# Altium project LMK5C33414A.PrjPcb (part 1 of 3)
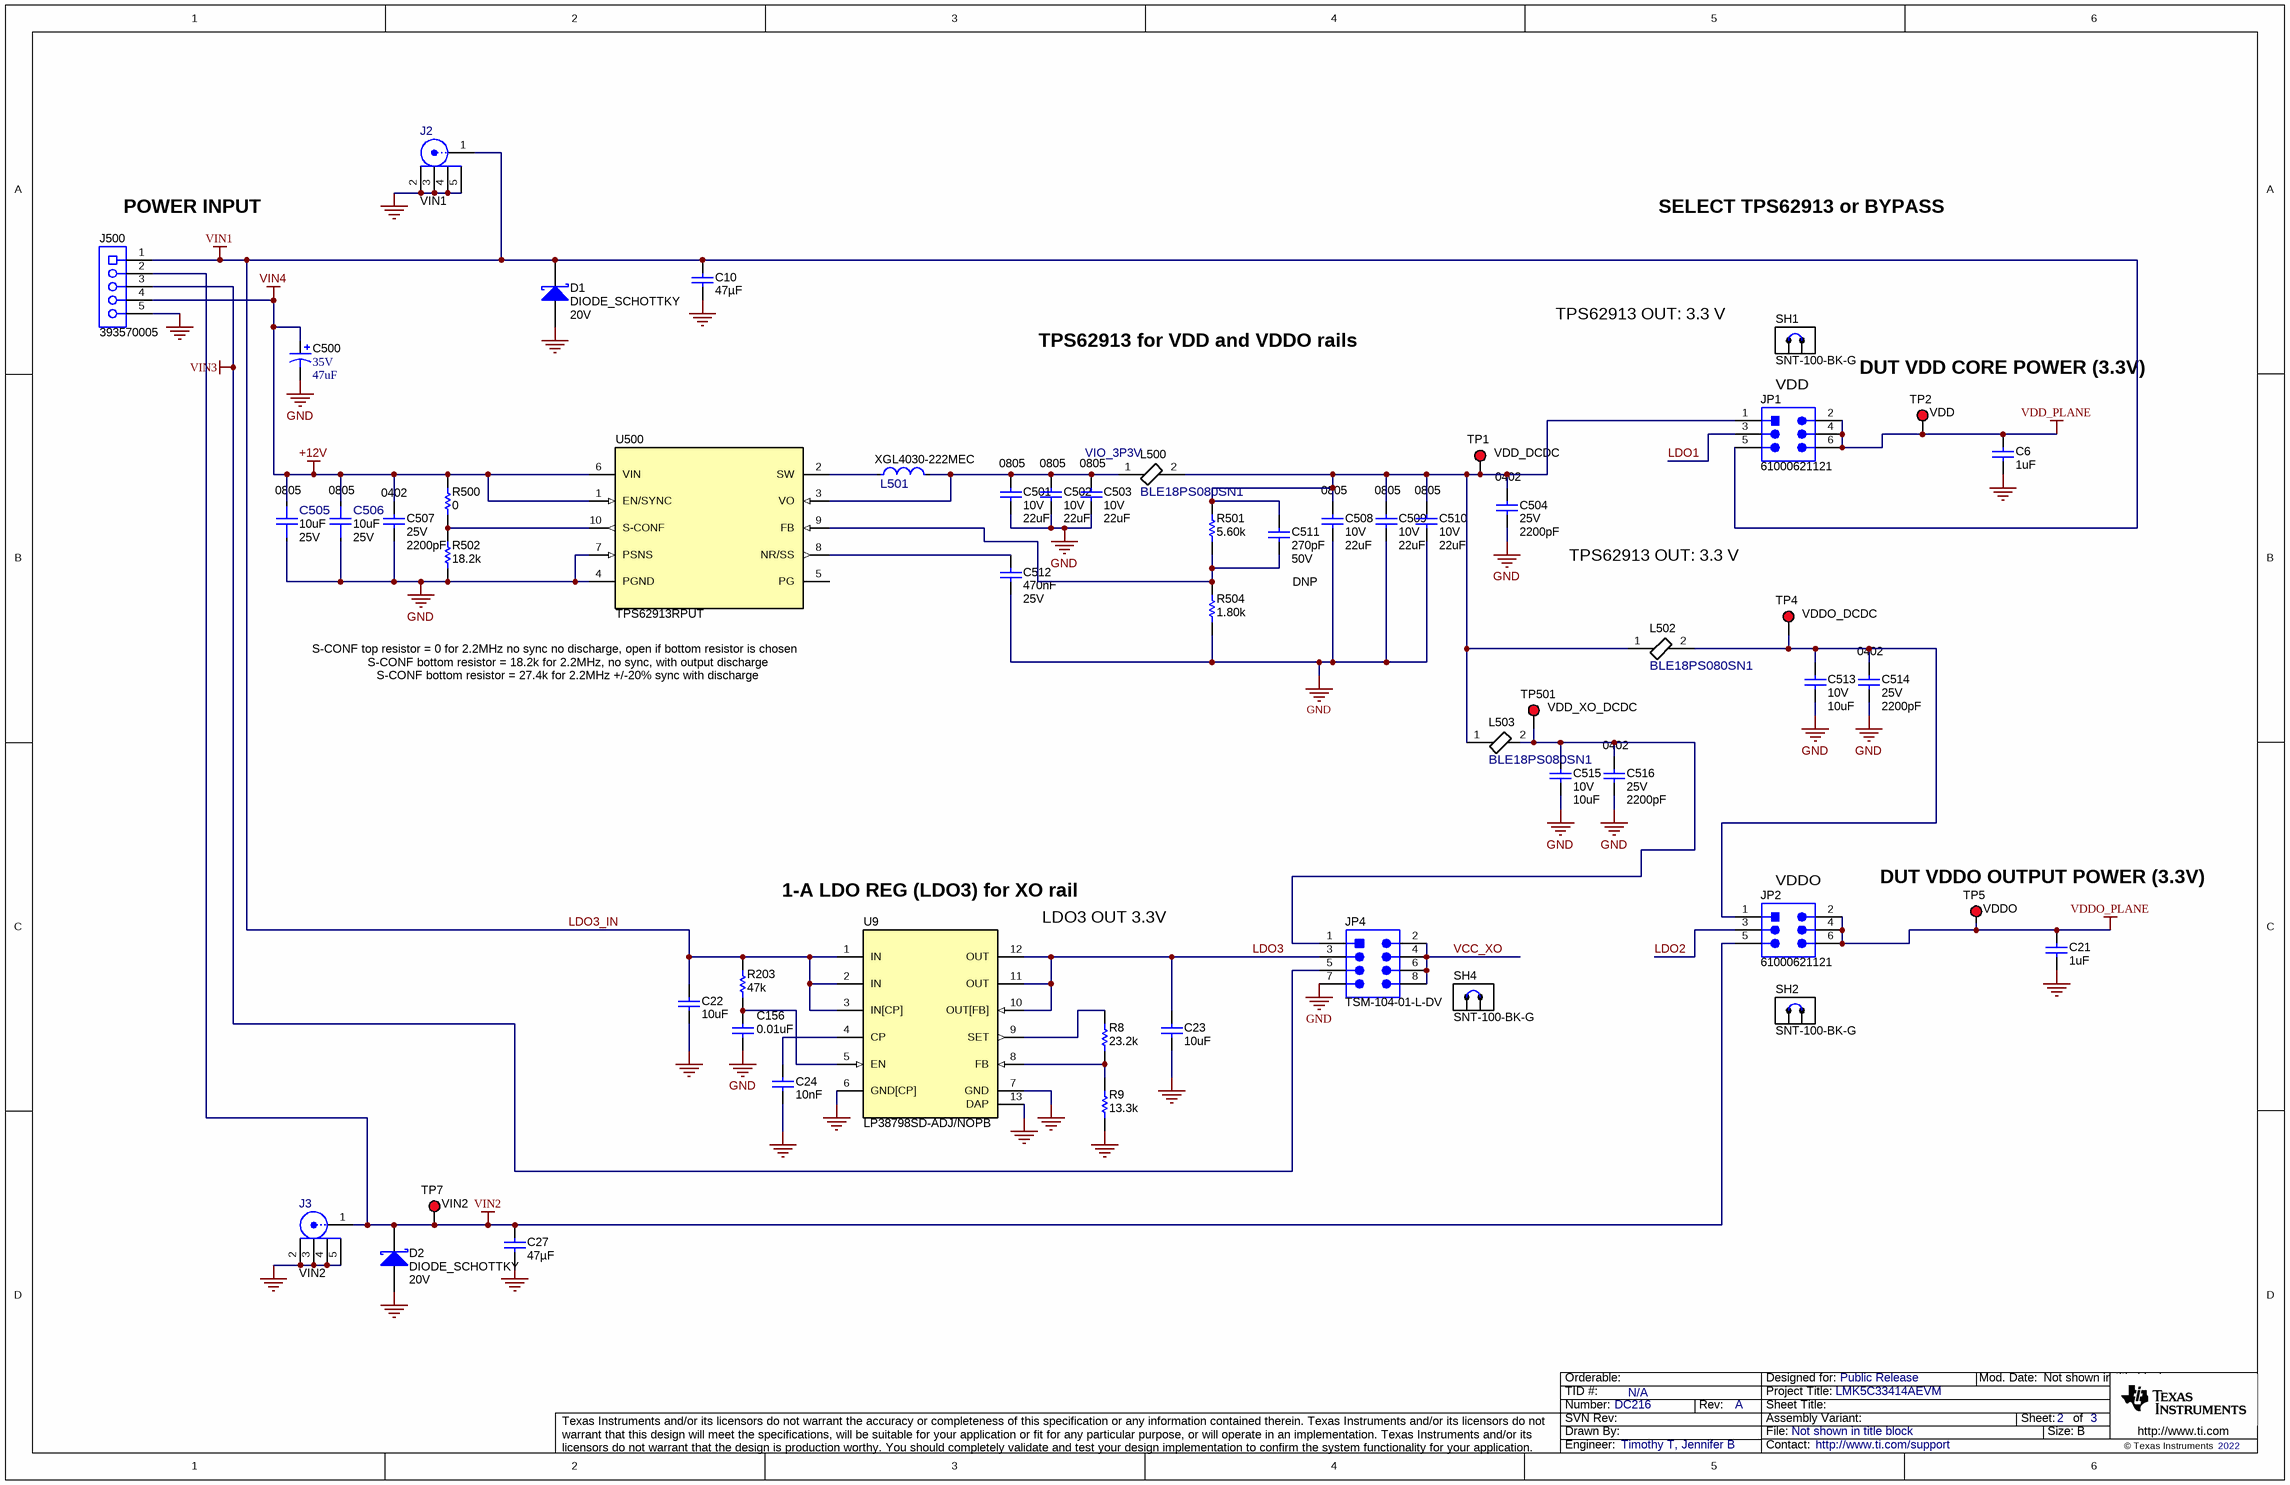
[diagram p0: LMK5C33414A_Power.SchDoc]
CopyrightYear: 2022; PCB_Layout: Timothy T, Jennifer B; PCB_Rev: A; PRJ_Customer: Public Release; PRJ_Engineer: Timothy T, Jennifer B; PRJ_Number: DC216; PRJ_Title: LMK5C33414AEVM; SCH_Rev: A; TechSupport: http://www.ti.com/support; TID: N/A
12 sheets, 526 parts. Net scope: global (net labels, ports and power ports of the same name join across sheets).
Board file: LMK5C33414A_PCB.PcbDoc
Sheets:
  LMK5C33414A_Power.SchDoc
  LMK5C33414A_Power_Alternate.SchDoc
  LMK5C33414A_PowerDist.SchDoc
  LMK5C33414A_XO.SchDoc
  LMK5C33414A_Inputs.SchDoc
  LMK5C33414A_DUT.SchDoc
  LMK5C33414A_Logic.SchDoc
  LMK5C33414A_Outputs_A.SchDoc
  LMK5C33414A_Outputs_B.SchDoc
  LMK5C33414A_Outputs_C.SchDoc
  LMK5C33414A_USB2ANY.SchDoc
  LMK5C33414A_Hardware.SchDoc

## Sheet LMK5C33414A_Power.SchDoc
size 431 x 279 mm; Date: Not shown in title block; ApprovedBy: Not shown in title block; CheckedBy: Not shown in title block; Author: Not shown in title block; CompanyName: Not shown in title block; Engineer: Not shown in title block; Organization: Not shown in title block; Address1: Not shown in title block; Address2: Not shown in title block; Address3: Not shown in title block; Address4: Not shown in title block; DocumentNumber: 2; Revision: Use project parameter SCH_Rev; SheetNumber: 2; SheetTotal: 3; PageSetup: Record=PageOptions¦CenterHorizontal=True¦CenterVertical=True¦PrintScale=1.00¦XCorrection=1.00¦YCorrection=1.00¦PrintKind=0¦BorderSize=5000000¦LeftOffset=0¦BottomOffset=0¦Orientation=2¦PaperLength=1000¦PaperWidth=1000¦Scale=100¦PaperSource=15¦PrintQuality=600¦MediaType=1¦DitherType=10¦PaperKind=Letter¦PrintScaleMode=1

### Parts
C6  ValueDisplayed: 1uF  [0603]  (hidden comment: Capacitor)
C10  ValueDisplayed: 47µF  [0805_HV]  (hidden comment: GRM21BR61A476ME15L)
C21  ValueDisplayed: 1uF  [0603]  (hidden comment: Capacitor)
C22  ValueDisplayed: 10uF  [0603]  (hidden comment: Capacitor)
C23  ValueDisplayed: 10uF  [0603]  (hidden comment: Capacitor)
C24  ValueDisplayed: 10nF  [0603]  (hidden comment: Capacitor)
C27  ValueDisplayed: 47µF  [0805_HV]  (hidden comment: GRM21BR61A476ME15L)
C156  ValueDisplayed: 0.01uF  [0603]  (hidden comment: Capacitor)
C500  VDC_V: 35V  ValueDisplayed: 47uF  [7343-43]  (hidden comment: T495X476K035ATE300)
C501  Cap_Case: 0805  VDC_V: 10V  ValueDisplayed: 22uF  [0805L]  (hidden comment: C2012X7S1A226M125AC)
C502  Cap_Case: 0805  VDC_V: 10V  ValueDisplayed: 22uF  [0805L]  (hidden comment: C2012X7S1A226M125AC)
C503  Cap_Case: 0805  VDC_V: 10V  ValueDisplayed: 22uF  [0805L]  (hidden comment: C2012X7S1A226M125AC)
C504  VDC_V: 25V  ValueDisplayed: 2200pF  [0402]  (hidden comment: GRM155R71E222KA01D)
C505  PackageReference: 0805  ValueDisplayed: 10uF  VDC_V: 25V  [FP-C2012X7S1E106K125AC_0805-MFG]  (hidden comment: C2012X7S1E106K125AC)
C506  PackageReference: 0805  ValueDisplayed: 10uF  VDC_V: 25V  [FP-C2012X7S1E106K125AC_0805-MFG]  (hidden comment: C2012X7S1E106K125AC)
C507  VDC_V: 25V  ValueDisplayed: 2200pF  [0402]  (hidden comment: GRM155R71E222KA01D)
C508  Cap_Case: 0805  VDC_V: 10V  ValueDisplayed: 22uF  [0805L]  (hidden comment: C2012X7S1A226M125AC)
C509  Cap_Case: 0805  VDC_V: 10V  ValueDisplayed: 22uF  [0805L]  (hidden comment: C2012X7S1A226M125AC)
C510  Cap_Case: 0805  VDC_V: 10V  ValueDisplayed: 22uF  [0805L]  (hidden comment: C2012X7S1A226M125AC)
C511  Cap_F: 270pF  VDC_V: 50V  [0402]  (hidden comment: UMK105CG271JV-F)
C512  Cap_F: 470nF  VDC_V: 25V  [0603]  (hidden comment: C1608X7R1E474K080AE)
C513  VDC_V: 10V  ValueDisplayed: 10uF  [0603]  (hidden comment: GRM188Z71A106MA73D)
C514  VDC_V: 25V  ValueDisplayed: 2200pF  [0402]  (hidden comment: GRM155R71E222KA01D)
C515  VDC_V: 10V  ValueDisplayed: 10uF  [0603]  (hidden comment: GRM188Z71A106MA73D)
C516  VDC_V: 25V  ValueDisplayed: 2200pF  [0402]  (hidden comment: GRM155R71E222KA01D)
D1  DIODE_SCHOTTKY  value 20V  [SMA]
D2  DIODE_SCHOTTKY  value 20V  [SMA]
J2  VIN1  [FP-CON-SMA-EDGE-S_CONN_JACK-MFG]
J3  VIN2  [FP-CON-SMA-EDGE-S_CONN_JACK-MFG]
J500  393570005  [Molex_0393570005]
JP1  61000621121  [Wurth_61000621121]
JP2  61000621121  [Wurth_61000621121]
JP4  TSM-104-01-L-DV  [Samtec_TSM-104-01-x-DV]
L500  BLE18PS080SN1  [FP-BLE18PS080SN1_0603-MFG]
L501  XGL4030-222MEC  [FP-XGL4030-222MEC_SMT_IND_4MM0_4MM0-MFG]
L502  BLE18PS080SN1  [FP-BLE18PS080SN1_0603-MFG]
L503  BLE18PS080SN1  [FP-BLE18PS080SN1_0603-MFG]
R8  ValueDisplayed: 23.2k  [0603]  (hidden comment: CRCW060323K2FKEA)
R9  ValueDisplayed: 13.3k  [0603]  (hidden comment: CRCW060313K3FKEA)
R203  ValueDisplayed: 47k  [0603]  (hidden comment: Resistor)
R500  ValueDisplayed: 0  [0603]  (hidden comment: ERJ-3GEY0R00V)
R501  ValueDisplayed: 5.60k  [0603]  (hidden comment: RG1608P-562-B-T5)
R502  ValueDisplayed: 18.2k  [0603]  (hidden comment: CRCW060318K2FKEA)
R504  ValueDisplayed: 1.80k  [0603]  (hidden comment: RT0603BRD071K8L)
SH1  SNT-100-BK-G  [SNT-100-BK-G]
SH2  SNT-100-BK-G  [SNT-100-BK-G]
SH4  SNT-100-BK-G  [SNT-100-BK-G]
TP1  VDD_DCDC  [Keystone5000]
TP2  VDD  [Keystone5000]
TP4  VDDO_DCDC  [Keystone5000]
TP5  VDDO  [Keystone5000]
TP7  VIN2  [Keystone5000]
TP501  VDD_XO_DCDC  [Keystone5000]
U9  LP38798SD-ADJ/NOPB  [DNT0012B]
U500  TPS62913RPUT  [RPU0010A]

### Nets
+12V: C500.1(+) C505.2 C506.2 C507.1 J500.4 R500.2 U500.1(EN/SYNC) U500.6(VIN)  [also labelled VIN4]
GND: C6.1 C10.2 C21.1 C22.2 C23.2 C24.2 C27.2 C156.2 C500.2(-) C501.2 C502.2 C503.2 C504.2 C505.1 C506.1 C507.2 C508.2 C509.2 C510.2 C512.2 C513.2 C514.2 C515.2 C516.2 D1.2(A) D2.2(A) J2.2 J2.3 J2.4 J2.5 J3.2 J3.3 J3.4 J3.5 J500.5 JP4.7 R9.1 R502.1 R504.1 U9.6(GND[CP]) U9.7(GND) U9.13(DAP) U500.4(PGND) U500.7(PSNS)
LDO3_IN: C10.1 C22.1 D1.1(K) J2.1 J500.1 JP1.5 R203.1 U9.1(IN) U9.2(IN) U9.3(IN[CP])  [also labelled VIN1]
VCC_XO: JP4.2 JP4.4 JP4.6 JP4.8
VDD_PLANE: C6.2 JP1.2 JP1.4 JP1.6 TP2.1
VDDO_PLANE: C21.2 JP2.2 JP2.4 JP2.6 TP5.1
VIN2: C27.1 D2.1(K) J3.1 J500.2 JP2.5 TP7.1
VIN3: J500.3 JP4.5
LDO1: JP1.3
LDO2: JP2.3
LDO3: C23.1 JP4.3 U9.10(OUT[FB]) U9.11(OUT) U9.12(OUT)
NetC24_1: C24.1 U9.4(CP)
NetC156_1: C156.1 R203.2 U9.5(EN)
NetC501_1: C501.1 C502.1 C503.1 L500.1 L501.2 U500.3(VO)
NetC504_1: C504.1 C508.1 C509.1 C510.1 C511.1 JP1.1 L500.2 L502.1 L503.1 R501.2 TP1.1
NetC511_2: C511.2 R501.1 R504.2 U500.9(FB)
NetC512_1: C512.1 U500.8(NR/SS)
NetC513_1: C513.1 C514.1 JP2.1 L502.2 TP4.1
NetC515_1: C515.1 C516.1 JP4.1 L503.2 TP501.1
NetL501_1: L501.1 U500.2(SW)
NetR8_1: R8.1 R9.2 U9.8(FB)
NetR8_2: R8.2 U9.9(SET)
NetR500_1: R500.1 R502.2 U500.10(S-CONF)

Not connected (* = marked no-connect by the designer): U500 5(PG)

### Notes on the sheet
- (near J500) POWER INPUT
- SELECT TPS62913 or BYPASS
- TPS62913 for VDD and VDDO rails
- TPS62913 OUT: 3.3 V
- (near TP2) DUT VDD CORE POWER (3.3V)
- VDD
- VIO_3P3V
- DNP
- S-CONF top resistor = 0 for 2.2MHz no sync no discharge, open if bottom resistor is chosen
- S-CONF bottom resistor = 18.2k for 2.2MHz, no sync, with output discharge
- S-CONF bottom resistor = 27.4k for 2.2MHz +/-20% sync with discharge
- 1-A LDO REG (LDO3) for XO rail
- (near JP2) VDDO
- (near TP5) DUT VDDO OUTPUT POWER (3.3V)
- LDO3 OUT 3.3V

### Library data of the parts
C6 C21 = CMP-0006869-5: CAP, CERM, 1 uF, 10 V, +/- 10%, X5R, 0603; Manufacturer: Kemet; PartNumber: C0603C105K8PACTU; Polarized: N; TaMax_C: 85°C; TaMin_C: -55°C; VDC_V: 10V; Cap_F: 1µF; Value: 1uF; Value1: Unknown; AEC Category: Q200; SizeArea_mm2: 1.28; SizeAreaWB_mm2: 4.68; SizeX_mm: 1.6; SizeY_mm: 0.8; SizeZ_mm: 1; U/M: EA
C10 C27 = CMP-0078699-1: CAP, CERM, 47 µF, 10 V,+/- 20%, X5R, 0805; Manufacturer: MuRata; Polarized: N; Value: 47uF; U/M: EA; VDC_V: 10V; TaMin_C: -55°C; TaMax_C: 85°C; Cap_Case: 0805; SizeArea_mm2: 2.5; SizeAreaWB_mm2: 6.75; SizeX_mm: 2; SizeY_mm: 1.25; SizeZ_mm: 1.45; AEC Category: Q200; Green_Lifecycle: Active; Green_REACh: Passed
C22-C24 = CMP-0007003-5: CAP, CERM, 10 uF, 10 V, +/- 20%, X5R, 0603; PartNumber: C1608X5R1A106M080AC; Manufacturer: TDK; Polarized: N; Value: 10uF; U/M: EA; Cap_F: 10µF; ESR_ohm: 7.8m; Value1: 0.0078 ohm; VDC_V: 10V; IRMS_A: 1.85A; TaMin_C: -55°C; TaMax_C: 85°C; SizeArea_mm2: 1.28; SizeAreaWB_mm2: 4.68; SizeX_mm: 1.6; SizeY_mm: 0.8; SizeZ_mm: 1; AEC Category: Q200
C156 = CMP-0006850-4: CAP, CERM, 0.01 uF, 50 V, +/- 5%, X7R, 0603; PartNumber: C0603C103J5RACTU; Manufacturer: Kemet; Polarized: N; Value: 0.01uF; U/M: EA; Cap_F: 10nF; Value1: Unknown; VDC_V: 50V; TaMin_C: -55°C; TaMax_C: 125°C; SizeArea_mm2: 1.28; SizeAreaWB_mm2: 4.68; SizeX_mm: 1.6; SizeY_mm: 0.8; SizeZ_mm: 1; AEC Category: Q200
C500 = CMP-0011835-2: CAP, TA, 47 uF, 35 V, +/- 10%, 0.3 ohm, SMD; Manufacturer: Kemet; TaMin_C: -55°C; ESR_ohm: 3d; Polarized: Y; SizeAreaWB_mm2: 58.59; Value1: 0.3 ohm; U/M: EA; Value: 47uF; TaMax_C: 125°C; SizeZ_mm: 4.3; SizeX_mm: 7.3; Cap_Case: X; SizeArea_mm2: 31.39; CompType: Capacitor; Cap_F: 47µF; IRMS_A: 6.67dA; AEC Category: Q200
C501-C503 C508-C510 = CMP-0007890-1: CAP, CERM, 22 uF, 10 V, +/- 20%, X7S, 0805; Manufacturer: TDK; TaMin_C: -55°C; ESR_ohm: 2.05m; Polarized: N; SizeAreaWB_mm2: 6.75; Value1: 0.00205 ohm; U/M: EA; Value: 22uF; TaMax_C: 125°C; SizeZ_mm: 1.45; SizeX_mm: 2; SizeY_mm: 1.25; SizeArea_mm2: 2.5; Cap_F: 22µF; IRMS_A: 4.55587A; AEC Category: Q200
C504 C507 C514 C516 = CMP-0006663-2: CAP, CERM, 2200 pF, 25 V, +/- 10%, X7R, 0402; Manufacturer: MuRata; TaMin_C: -55°C; Polarized: N; SizeAreaWB_mm2: 3; Value1: Unknown; U/M: EA; Value: 2200pF; TaMax_C: 125°C; SizeZ_mm: 0.6; SizeX_mm: 1; SizeY_mm: 0.5; Cap_F: 2.2nF; AEC Category: Q200
C505 C506 = CMP-0089528-1: 10µF ±10% 25V Ceramic Capacitor X7S 0805 (2012 Metric); Manufacturer: TDK; TempCo: 22%; SizeZ_mm: 1.5mm; AEC Qualified: No
C511 = CMP-0087076-3: CAP CER 270PF 50V NP0 0402; Manufacturer: Taiyo Yuden; Tolerance_%: 5%; SizeZ_mm: 0.55mm; AEC Qualified: No; TempCo: 30ppm/°C
C512 = CMP-0750175-1: CAP, CERM, 0.47 µF, 25 V,+/- 10%, X7R, 0603; Manufacturer: TDK; AEC Qualified: N; TaMax_C: 125°C; U/M: EA; AEC Category: Q200; Value: 0.47uF; SizeX_mm: 1.6; SizeAreaWB_mm2: 4.68; SizeZ_mm: 1; SizeY_mm: 0.8; SizeArea_mm2: 1.28; ValueDisplayed: 0.47µF; TaMin_C: -55°C
C513 C515 = CMP-0007497-5: CAP, CERM, 10 uF, 10 V, +/- 20%, X7R, 0603; Manufacturer: MuRata; TaMin_C: -55°C; Polarized: N; SizeAreaWB_mm2: 4.68; Value1: Unknown; U/M: EA; Value: 10uF; TaMax_C: 125°C; SizeZ_mm: 1; SizeX_mm: 1.6; SizeY_mm: 0.8; SizeArea_mm2: 1.28; Cap_F: 10µF; AEC Category: Q200
D1 D2 = CMP-0028399-2: Diode, Schottky, 20 V, 2 A, SMA; PartNumber: B220A-13-F; Manufacturer: Diodes Inc.; Vf_V: 5dV; Value1: 2A; Value2: 0.5V; TJmax_C: 150°C; RJC_CperW: 20; AEC Category: Q101; Green_Lifecycle: Active; Green_REACh: Passed; SizeArea_mm2: 16.3228; SizeAreaWB_mm2: 37.3428; SizeX_mm: 5.59; SizeY_mm: 2.92; SizeZ_mm: 2.87
J2 J3 = CMP-0088000-4: CONN SMA JACK STR EDGE MNT; Manufacturer: RF Solutions Ltd.; PartNumber: CON-SMA-EDGE-S; ContactFinish: Gold; Shrouded: true
J500 = CMP-0080926-1: Terminal Block, 3.5mm, 5x1, Tin, TH; Manufacturer: Molex; Pitch_mm: 3.5; Gender: Female; Voltage_V: 300V; Row_Count: 1; Current_A: 17.5A; Cert_UL: Y
JP1 JP2 = CMP-0079534-2: Header, 2.54mm, 3x2, Gold, SMT; Manufacturer: Wurth Elektronik; Pitch_mm: 2.54; Gender: Male; Cert_UL: Y; Current_A: 3A; Voltage_V: 250V; Shrouded: N; Row_Count: 2
JP4 = CMP-0075593-2: Header, 2.54mm, 4x2, Gold, SMT; Manufacturer: Samtec; Pitch_mm: 2.54; Gender: Male; Cert_CSA: Y; Green_REACh: Passed; Current_A: 4.9A; Voltage_V: 475V; Shrouded: N; Green_Lifecycle: Active; Row_Count: 2
L500 L502 L503 = CMP-0087072-1: Bead inductor BLE series, 8A; Manufacturer: Murata; SizeZ_mm: 0.75mm; AEC Qualified: No; Material: Ferrite
L501 = CMP-0089541-1: Inductor Power Shielded Wirewound 2.2uH 20% 1MHz Composite 8.7A 15mOhm DCR Automotive T/R; Manufacturer: Coilcraft; Shrouded: true; SizeZ_mm: 3.1mm; AEC Grade: Grade 1; AEC Qualified: Yes; Isat: 3.1A; Ind_H: 2.2µH; Self Resonant Frequency: 40MHz; DCR_ohm: 0.015; Standoff Height: 0.16mm; TaMin_C: -40°C; TaMax_C: +125°C
R8 = CMP-0022228-4: RES, 23.2 k, 1%, 0.1 W, AEC-Q200 Grade 0, 0603; Manufacturer: Vishay-Dale; Value: 23.2k; Value_Code: 23k2; Power_W: 100mW; Value2: 0.1W; VDC_V: 75V; TempCo: 100 ppm/C; EIA_Code: E96; SizeArea_mm2: 1.28; SizeX_mm: 1.6; SizeY_mm: 0.8; SizeZ_mm: 1; AEC Category: Q200; AEC Qualified: Y; AEC Grade: 0
R9 = CMP-0022043-4: RES, 13.3 k, 1%, 0.1 W, AEC-Q200 Grade 0, 0603; Manufacturer: Vishay-Dale; Value: 13.3k; Value_Code: 13k3; Power_W: 100mW; Value2: 0.1W; VDC_V: 75V; TempCo: 100 ppm/C; EIA_Code: E96; SizeArea_mm2: 1.28; SizeX_mm: 1.6; SizeY_mm: 0.8; SizeZ_mm: 1; AEC Category: Q200; AEC Qualified: Y; AEC Grade: 0
R203 = CMP-0025814-4: RES, 47 k, 5%, 0.1 W, AEC-Q200 Grade 0, 0603; PartNumber: CRCW060347K0JNEA; Manufacturer: Vishay-Dale; Value: 47k; Value_Code: 47k0; Power_W: 100mW; Value2: 0.1W; VDC_V: 75V; TempCo: 200 ppm/C; EIA_Code: E24; SizeArea_mm2: 1.28; SizeX_mm: 1.6; SizeY_mm: 0.8; SizeZ_mm: 1; AEC Category: Q200; AEC Qualified: Y; AEC Grade: 0
R500 = CMP-0025874-4: RES, 0, 5%, 0.1 W, AEC-Q200 Grade 0, 0603; Manufacturer: Panasonic; Power_W: 100mW; TempCo: 600 ppm/C; Value_Code: 0000; Value: 0; EIA_Code: E24; SizeX_mm: 1.6; SizeY_mm: 0.8; SizeZ_mm: 1; Value2: 0.1W; SizeArea_mm2: 1.28; AEC Qualified: Y; VDC_V: 50V; AEC Category: Q200; SizeAreaWB_mm2: 4.68
R501 = CMP-0023576-3: RES, 5.60 k, 0.1%, 0.1 W, 0603; Manufacturer: Susumu Co Ltd; Power_W: 100mW; TempCo: 25 ppm/C; Value_Code: 5k60; U/M: EA; Value: 5.60k; Res_ohm: 5.6k; SizeX_mm: 1.6; SizeY_mm: 0.8; SizeZ_mm: 1; Value2: 0.1W; SizeArea_mm2: 1.28; VDC_V: 75V; AEC Category: Q200
R502 = CMP-0022097-4: RES, 18.2 k, 1%, 0.1 W, AEC-Q200 Grade 0, 0603; Manufacturer: Vishay-Dale; Power_W: 100mW; TempCo: 100 ppm/C; Value_Code: 18k2; Value: 18.2k; EIA_Code: E96; SizeX_mm: 1.6; SizeY_mm: 0.8; SizeZ_mm: 1; Value2: 0.1W; SizeArea_mm2: 1.28; AEC Qualified: Y; VDC_V: 75V; AEC Category: Q200; AEC Grade: 0
R504 = CMP-0023914-3: RES, 1.80 k, 0.1%, 0.1 W, 0603; Manufacturer: Yageo America; Power_W: 100mW; TempCo: 25 ppm/C; Value_Code: 1k80; U/M: EA; Value: 1.80k; EIA_Code: E192; Res_ohm: 1.8k; SizeX_mm: 1.6; SizeY_mm: 0.8; SizeZ_mm: 1; Value2: 0.1W; SizeArea_mm2: 1.28; VDC_V: 75V; AEC Category: Q200
SH1 SH2 SH4 = CMP-0003623-3: Shunt, 100mil, Gold plated, Black; Manufacturer: Samtec; Alternate Manufacturer: 3M; Alternate PartNumber: 969102-0000-DA; Value: 1x2; Note: You can "mate" this to a header by matching the designator.  i.e. use SH-J3 for header J3
TP1 TP2 TP4 TP5 TP7 TP501 = CMP-0055137-1: Test Point, Miniature, Red, TH; Manufacturer: Keystone; CNHeader: FALSE; ContactFinish: Silver; CT: TRUE; Green_Lifecycle: Active; Green_REACh: Passed
U9 = CMP-0066007-2: 800-mA Ultra-Low-Noise, High-PSRR LDO, DNT0012B (WSON-12); Manufacturer: Texas Instruments; SizeZ_mm: 0.8; SizeX_mm: 4.0; SizeArea_mm2: 16.0; CompType: IC; U/M: EA; SizeAreaWB_mm2: 25.0
U500 = CMP-0860321-2: 3A Low Noise and Low Ripple buck converter, RPU0010A (VQFN-10); Alternate Manufacturer: Texas Instruments; SizeArea_mm2: 4; SizeAreaWB_mm2: 9; AEC Category: Q200; SizeY_mm: 2; CompType: IC; SizeZ_mm: 1; AEC Qualified: N

## Sheet LMK5C33414A_Power_Alternate.SchDoc
size 431 x 279 mm; Date: Not shown in title block; ApprovedBy: Not shown in title block; CheckedBy: Not shown in title block; Author: Not shown in title block; CompanyName: Not shown in title block; Engineer: Not shown in title block; Organization: Not shown in title block; Address1: Not shown in title block; Address2: Not shown in title block; Address3: Not shown in title block; Address4: Not shown in title block; DocumentNumber: 2; Revision: Use project parameter SCH_Rev; SheetNumber: 2; SheetTotal: 3; PageSetup: Record=PageOptions¦CenterHorizontal=True¦CenterVertical=True¦PrintScale=1.00¦XCorrection=1.00¦YCorrection=1.00¦PrintKind=0¦BorderSize=5000000¦LeftOffset=0¦BottomOffset=0¦Orientation=2¦PaperLength=1000¦PaperWidth=1000¦Scale=100¦PaperSource=15¦PrintQuality=600¦MediaType=1¦DitherType=10¦PaperKind=Letter¦PrintScaleMode=1
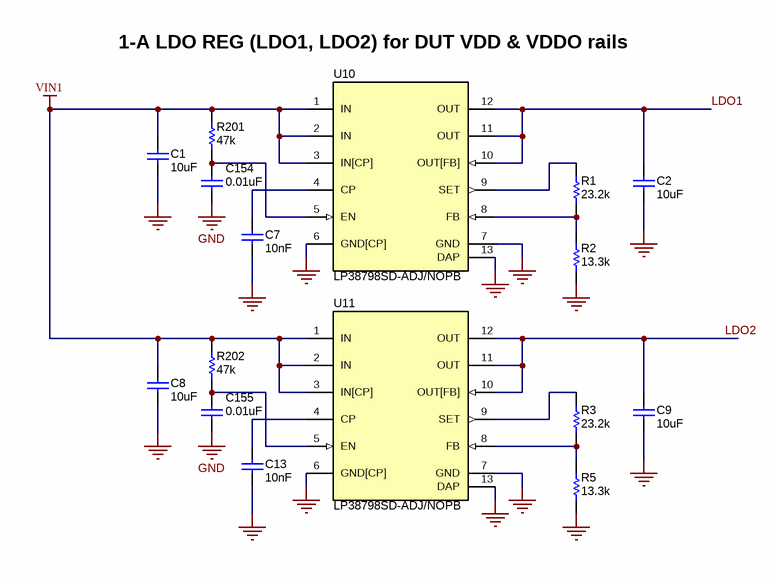
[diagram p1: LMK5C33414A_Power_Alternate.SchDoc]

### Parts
C1  ValueDisplayed: 10uF  [0603]  (hidden comment: Capacitor)
C2  ValueDisplayed: 10uF  [0603]  (hidden comment: Capacitor)
C7  ValueDisplayed: 10nF  [0603]  (hidden comment: Capacitor)
C8  ValueDisplayed: 10uF  [0603]  (hidden comment: Capacitor)
C9  ValueDisplayed: 10uF  [0603]  (hidden comment: Capacitor)
C13  ValueDisplayed: 10nF  [0603]  (hidden comment: Capacitor)
C154  ValueDisplayed: 0.01uF  [0603]  (hidden comment: Capacitor)
C155  ValueDisplayed: 0.01uF  [0603]  (hidden comment: Capacitor)
R1  ValueDisplayed: 23.2k  [0603]  (hidden comment: CRCW060323K2FKEA)
R2  ValueDisplayed: 13.3k  [0603]  (hidden comment: CRCW060313K3FKEA)
R3  ValueDisplayed: 23.2k  [0603]  (hidden comment: CRCW060323K2FKEA)
R5  ValueDisplayed: 13.3k  [0603]  (hidden comment: CRCW060313K3FKEA)
R201  ValueDisplayed: 47k  [0603]  (hidden comment: Resistor)
R202  ValueDisplayed: 47k  [0603]  (hidden comment: Resistor)
U10  LP38798SD-ADJ/NOPB  [DNT0012B]
U11  LP38798SD-ADJ/NOPB  [DNT0012B]

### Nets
GND: C1.2 C2.2 C7.2 C8.2 C9.2 C13.2 C154.2 C155.2 R2.1 R5.1 U10.6(GND[CP]) U10.7(GND) U10.13(DAP) U11.6(GND[CP]) U11.7(GND) U11.13(DAP)
VIN1: C1.1 C8.1 R201.1 R202.1 U10.1(IN) U10.2(IN) U10.3(IN[CP]) U11.1(IN) U11.2(IN) U11.3(IN[CP])  [project net LDO3_IN]
LDO1: C2.1 U10.10(OUT[FB]) U10.11(OUT) U10.12(OUT)
LDO2: C9.1 U11.10(OUT[FB]) U11.11(OUT) U11.12(OUT)
NetC7_1: C7.1 U10.4(CP)
NetC13_1: C13.1 U11.4(CP)
NetC154_1: C154.1 R201.2 U10.5(EN)
NetC155_1: C155.1 R202.2 U11.5(EN)
NetR1_1: R1.1 R2.2 U10.8(FB)
NetR1_2: R1.2 U10.9(SET)
NetR3_1: R3.1 R5.2 U11.8(FB)
NetR3_2: R3.2 U11.9(SET)

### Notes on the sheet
- 1-A LDO REG (LDO1, LDO2) for DUT VDD & VDDO rails

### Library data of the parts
C1 C2 C7-C9 C13 = CMP-0007003-5: as C22 on sheet LMK5C33414A_Power
C154 C155 = CMP-0006850-4: as C156 on sheet LMK5C33414A_Power
R1 R3 = CMP-0022228-4: as R8 on sheet LMK5C33414A_Power
R2 R5 = CMP-0022043-4: as R9 on sheet LMK5C33414A_Power
R201 R202 = CMP-0025814-4: as R203 on sheet LMK5C33414A_Power
U10 U11 = CMP-0066007-2: as U9 on sheet LMK5C33414A_Power

## Sheet LMK5C33414A_PowerDist.SchDoc
size 431 x 279 mm; Date: Not shown in title block; ApprovedBy: Not shown in title block; CheckedBy: Not shown in title block; Author: Not shown in title block; CompanyName: Not shown in title block; Engineer: Not shown in title block; Organization: Not shown in title block; Address1: Not shown in title block; Address2: Not shown in title block; Address3: Not shown in title block; Address4: Not shown in title block; DocumentNumber: 2; Revision: Use project parameter SCH_Rev; SheetNumber: 2; SheetTotal: 3; PageSetup: Record=PageOptions¦CenterHorizontal=True¦CenterVertical=True¦PrintScale=1.00¦XCorrection=1.00¦YCorrection=1.00¦PrintKind=0¦BorderSize=5000000¦LeftOffset=0¦BottomOffset=0¦Orientation=2¦PaperLength=1000¦PaperWidth=1000¦Scale=100¦PaperSource=15¦PrintQuality=600¦MediaType=1¦DitherType=10¦PaperKind=Letter¦PrintScaleMode=1
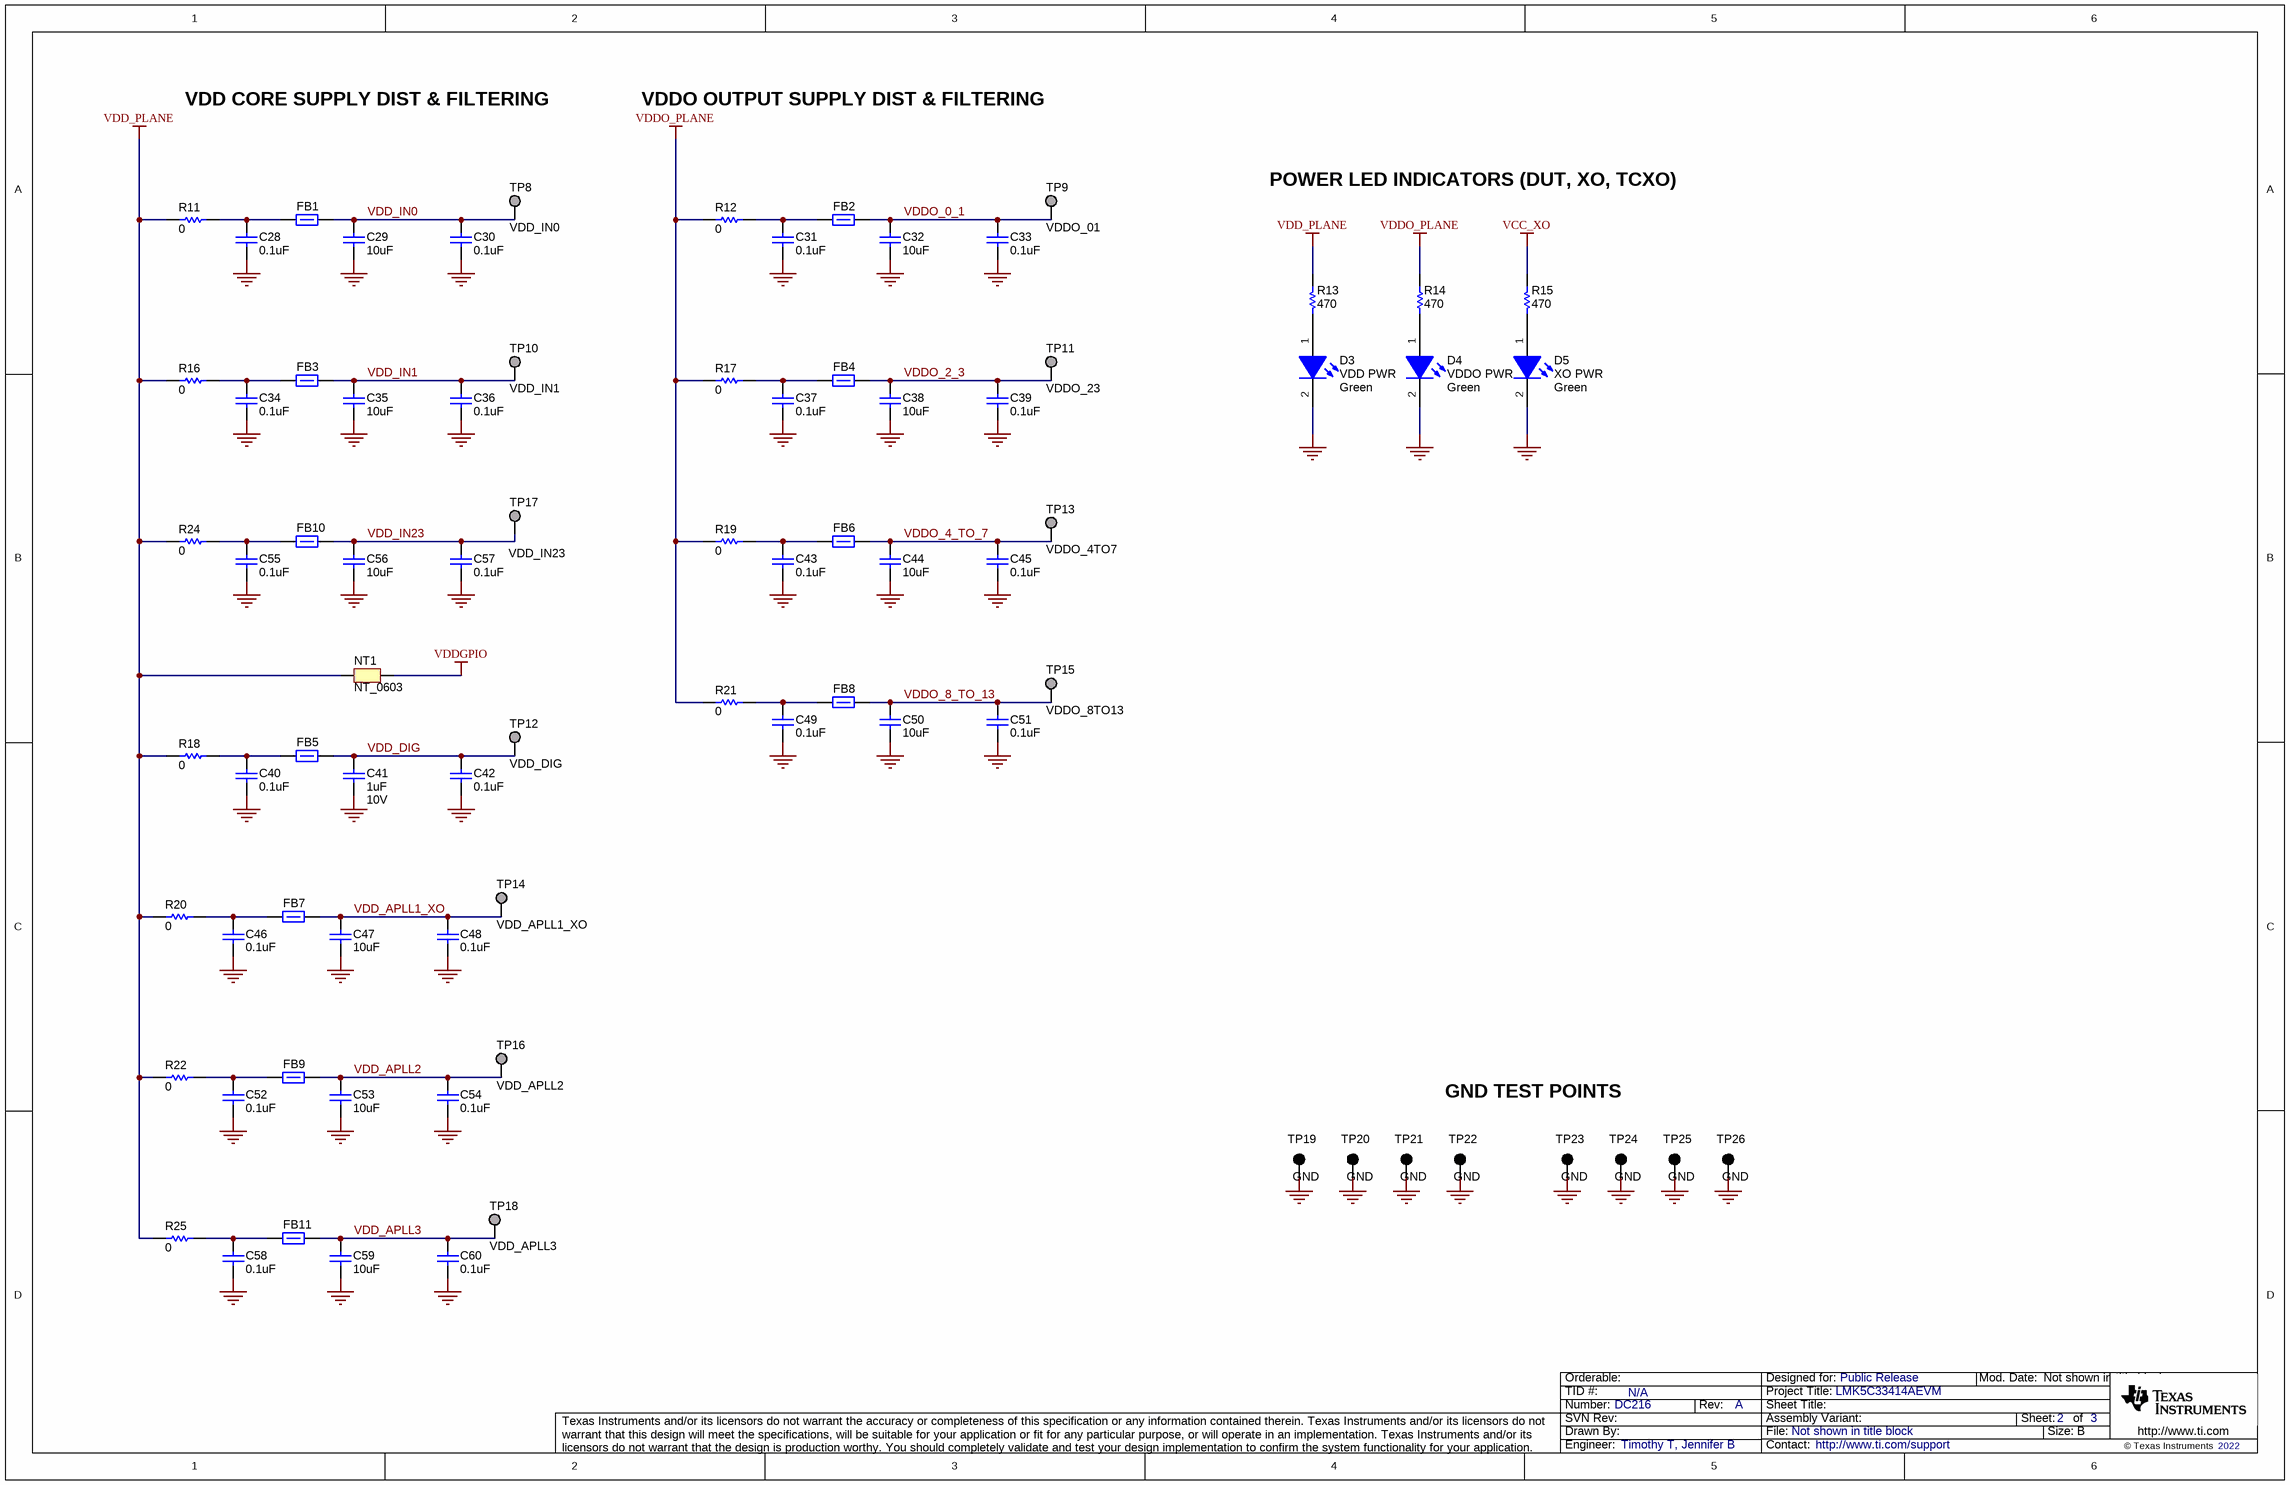
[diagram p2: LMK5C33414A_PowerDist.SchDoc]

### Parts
C28  ValueDisplayed: 0.1uF  [0603L]  (hidden comment: Capacitor)
C29  ValueDisplayed: 10uF  [0603L]  (hidden comment: Capacitor)
C30  ValueDisplayed: 0.1uF  [0402L]  (hidden comment: Capacitor)
C31  ValueDisplayed: 0.1uF  [0603L]  (hidden comment: Capacitor)
C32  ValueDisplayed: 10uF  [0603L]  (hidden comment: Capacitor)
C33  ValueDisplayed: 0.1uF  [0402L]  (hidden comment: Capacitor)
C34  ValueDisplayed: 0.1uF  [0603L]  (hidden comment: Capacitor)
C35  ValueDisplayed: 10uF  [0603L]  (hidden comment: Capacitor)
C36  ValueDisplayed: 0.1uF  [0402L]  (hidden comment: Capacitor)
C37  ValueDisplayed: 0.1uF  [0603L]  (hidden comment: Capacitor)
C38  ValueDisplayed: 10uF  [0603L]  (hidden comment: Capacitor)
C39  ValueDisplayed: 0.1uF  [0402L]  (hidden comment: Capacitor)
C40  ValueDisplayed: 0.1uF  [0603L]  (hidden comment: Capacitor)
C41  ValueDisplayed: 1uF  VDC_V: 10V  [0603L]  (hidden comment: C0603C105K8PACTU)
C42  ValueDisplayed: 0.1uF  [0402L]  (hidden comment: Capacitor)
C43  ValueDisplayed: 0.1uF  [0603L]  (hidden comment: Capacitor)
C44  ValueDisplayed: 10uF  [0603L]  (hidden comment: Capacitor)
C45  ValueDisplayed: 0.1uF  [0402L]  (hidden comment: Capacitor)
C46  ValueDisplayed: 0.1uF  [0603L]  (hidden comment: Capacitor)
C47  ValueDisplayed: 10uF  [0603L]  (hidden comment: Capacitor)
C48  ValueDisplayed: 0.1uF  [0402L]  (hidden comment: Capacitor)
C49  ValueDisplayed: 0.1uF  [0603L]  (hidden comment: Capacitor)
C50  ValueDisplayed: 10uF  [0603L]  (hidden comment: Capacitor)
C51  ValueDisplayed: 0.1uF  [0402L]  (hidden comment: Capacitor)
C52  ValueDisplayed: 0.1uF  [0603L]  (hidden comment: Capacitor)
C53  ValueDisplayed: 10uF  [0603L]  (hidden comment: Capacitor)
C54  ValueDisplayed: 0.1uF  [0402L]  (hidden comment: Capacitor)
C55  ValueDisplayed: 0.1uF  [0603L]  (hidden comment: Capacitor)
C56  ValueDisplayed: 10uF  [0603L]  (hidden comment: Capacitor)
C57  ValueDisplayed: 0.1uF  [0402L]  (hidden comment: Capacitor)
C58  ValueDisplayed: 0.1uF  [0603L]  (hidden comment: Capacitor)
C59  ValueDisplayed: 10uF  [0603L]  (hidden comment: Capacitor)
C60  ValueDisplayed: 0.1uF  [0402L]  (hidden comment: Capacitor)
D3  VDD PWR  value Green  [LED_LTST-C190]
D4  VDDO PWR  value Green  [LED_LTST-C190]
D5  XO PWR  value Green  [LED_LTST-C190]
FB1  BLM18SG221TN1D  [0603L]  (value not drawn)
FB2  BLM18SG221TN1D  [0603L]  (value not drawn)
FB3  BLM18SG221TN1D  [0603L]  (value not drawn)
FB4  BLM18SG221TN1D  [0603L]  (value not drawn)
FB5  BLM18SG221TN1D  [0603L]  (value not drawn)
FB6  BLM18SG221TN1D  [0603L]  (value not drawn)
FB7  BLM18SG221TN1D  [0603L]  (value not drawn)
FB8  BLM18SG221TN1D  [0603L]  (value not drawn)
FB9  BLM18SG221TN1D  [0603L]  (value not drawn)
FB10  BLM18SG221TN1D  [0603L]  (value not drawn)
FB11  BLM18SG221TN1D  [0603L]  (value not drawn)
NT1  NT_0603  [NetTie_0603]  (net tie, no BOM)
R11  ValueDisplayed: 0  [0603]  (hidden comment: CRCW06030000Z0EA)
R12  ValueDisplayed: 0  [0603]  (hidden comment: CRCW06030000Z0EA)
R13  ValueDisplayed: 470  [0603]  (hidden comment: Resistor)
R14  ValueDisplayed: 470  [0603]  (hidden comment: Resistor)
R15  ValueDisplayed: 470  [0603]  (hidden comment: Resistor)
R16  ValueDisplayed: 0  [0603]  (hidden comment: CRCW06030000Z0EA)
R17  ValueDisplayed: 0  [0603]  (hidden comment: CRCW06030000Z0EA)
R18  ValueDisplayed: 0  [0603]  (hidden comment: CRCW06030000Z0EA)
R19  ValueDisplayed: 0  [0603]  (hidden comment: CRCW06030000Z0EA)
R20  ValueDisplayed: 0  [0603]  (hidden comment: CRCW06030000Z0EA)
R21  ValueDisplayed: 0  [0603]  (hidden comment: CRCW06030000Z0EA)
R22  ValueDisplayed: 0  [0603]  (hidden comment: CRCW06030000Z0EA)
R24  ValueDisplayed: 0  [0603]  (hidden comment: CRCW06030000Z0EA)
R25  ValueDisplayed: 0  [0603]  (hidden comment: CRCW06030000Z0EA)
TP8  VDD_IN0  [TP_SM_1MM]  (no BOM)
TP9  VDDO_01  [TP_SM_1MM]  (no BOM)
TP10  VDD_IN1  [TP_SM_1MM]  (no BOM)
TP11  VDDO_23  [TP_SM_1MM]  (no BOM)
TP12  VDD_DIG  [TP_SM_1MM]  (no BOM)
TP13  VDDO_4TO7  [TP_SM_1MM]  (no BOM)
TP14  VDD_APLL1_XO  [TP_SM_1MM]  (no BOM)
TP15  VDDO_8TO13  [TP_SM_1MM]  (no BOM)
TP16  VDD_APLL2  [TP_SM_1MM]  (no BOM)
TP17  VDD_IN23  [TP_SM_1MM]  (no BOM)
TP18  VDD_APLL3  [TP_SM_1MM]  (no BOM)
TP19  GND  [Keystone5001]
TP20  GND  [Keystone5001]
TP21  GND  [Keystone5001]
TP22  GND  [Keystone5001]
TP23  GND  [Keystone5001]
TP24  GND  [Keystone5001]
TP25  GND  [Keystone5001]
TP26  GND  [Keystone5001]

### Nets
GND: C28.1 C29.2 C30.1 C31.1 C32.2 C33.1 C34.1 C35.2 C36.1 C37.1 C38.2 C39.1 C40.1 C41.2 C42.1 C43.1 C44.2 C45.1 C46.1 C47.2 C48.1 C49.1 C50.2 C51.1 C52.1 C53.2 C54.1 C55.1 C56.2 C57.1 C58.1 C59.2 C60.1 D3.2(K) D4.2(K) D5.2(K) TP19.1 TP20.1 TP21.1 TP22.1 TP23.1 TP24.1 TP25.1 TP26.1
VCC_XO: R15.1
VDD_PLANE: NT1.2 R11.2 R13.1 R16.2 R18.2 R20.2 R22.2 R24.1 R25.2
VDDGPIO: NT1.1
VDDO_PLANE: R12.2 R14.1 R17.2 R19.2 R21.2
VDD_APLL1_XO: C47.1 C48.2 FB7.2 TP14.1
VDD_APLL2: C53.1 C54.2 FB9.2 TP16.1
VDD_APLL3: C59.1 C60.2 FB11.2 TP18.1
VDD_DIG: C41.1 C42.2 FB5.2 TP12.1
VDD_IN0: C29.1 C30.2 FB1.2 TP8.1
VDD_IN1: C35.1 C36.2 FB3.2 TP10.1
VDD_IN23: C56.1 C57.2 FB10.2 TP17.1
VDDO_0_1: C32.1 C33.2 FB2.2 TP9.1
VDDO_2_3: C38.1 C39.2 FB4.2 TP11.1
VDDO_4_TO_7: C44.1 C45.2 FB6.2 TP13.1
VDDO_8_TO_13: C50.1 C51.2 FB8.2 TP15.1
NetC28_2: C28.2 FB1.1 R11.1
NetC31_2: C31.2 FB2.1 R12.1
NetC34_2: C34.2 FB3.1 R16.1
NetC37_2: C37.2 FB4.1 R17.1
NetC40_2: C40.2 FB5.1 R18.1
NetC43_2: C43.2 FB6.1 R19.1
NetC46_2: C46.2 FB7.1 R20.1
NetC49_2: C49.2 FB8.1 R21.1
NetC52_2: C52.2 FB9.1 R22.1
NetC55_2: C55.2 FB10.1 R24.2
NetC58_2: C58.2 FB11.1 R25.1
NetD3_1: D3.1(A) R13.2
NetD4_1: D4.1(A) R14.2
NetD5_1: D5.1(A) R15.2

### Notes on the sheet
- VDD CORE SUPPLY DIST & FILTERING
- VDDO OUTPUT SUPPLY DIST & FILTERING
- POWER LED INDICATORS (DUT, XO, TCXO)
- GND TEST POINTS

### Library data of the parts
C28 C31 C34 C37 C40 C43 C46 C49 C52 C55 C58 = CMP-0006856-6: CAP, CERM, 0.1 uF, 25 V, +/- 5%, X7R, 0603; PartNumber: C0603C104J3RACTU; Manufacturer: Kemet; Polarized: N; Value: 0.1uF; U/M: EA; Cap_F: 100nF; Value1: Unknown; VDC_V: 25V; TaMin_C: -55°C; TaMax_C: 125°C; Cap_Case: 0603; AEC Category: Q200; SizeArea_mm2: 1.28; SizeAreaWB_mm2: 4.68; SizeX_mm: 1.6; SizeY_mm: 0.8; SizeZ_mm: 1
C29 C32 C35 C38 C44 C47 C50 C53 C56 C59 = CMP-0007003-5: CAP, CERM, 10 uF, 10 V, +/- 20%, X5R, 0603; PartNumber: C1608X5R1A106M080AC; Manufacturer: TDK; Polarized: N; Value: 10uF; U/M: EA; Cap_F: 10µF; ESR_ohm: 7.8m; Value1: 0.0078 ohm; VDC_V: 10V; IRMS_A: 1.85A; TaMin_C: -55°C; TaMax_C: 85°C; Cap_Case: 0603; SizeArea_mm2: 1.28; SizeAreaWB_mm2: 4.68; SizeX_mm: 1.6; SizeY_mm: 0.8; SizeZ_mm: 1; AEC Category: Q200
C30 C33 C36 C39 C42 C45 C48 C51 C54 C57 C60 = CMP-0006259-2: CAP, CERM, 0.1 uF, 10 V, +/- 10%, X5R, 0402; PartNumber: C1005X5R1A104K050BA; Manufacturer: TDK; Polarized: N; Value: 0.1uF; U/M: EA; Cap_F: 100nF; Value1: Unknown; VDC_V: 10V; TaMin_C: -55°C; TaMax_C: 85°C; Cap_Case: 0402; SizeArea_mm2: 0.5; SizeAreaWB_mm2: 3; SizeX_mm: 1; SizeZ_mm: 0.6; AEC Category: Q200
C41 = CMP-0006869-5: CAP, CERM, 1 uF, 10 V, +/- 10%, X5R, 0603; Manufacturer: Kemet; Polarized: N; Value: 1uF; U/M: EA; Cap_F: 1µF; Value1: Unknown; TaMin_C: -55°C; TaMax_C: 85°C; Cap_Case: 0603; SizeArea_mm2: 1.28; SizeAreaWB_mm2: 4.68; SizeX_mm: 1.6; SizeY_mm: 0.8; SizeZ_mm: 1; AEC Category: Q200
D3-D5 = CMP-0002827-3: LED, Green, SMD; Manufacturer: Lite-On; PartNumber: LTST-C190GKT; Vf_V: 2.1V; Io_A: 20mA; Power_TotalModule: 100mW; Value1: 0.1W
FB1-FB11 = CMP-0003353-2: Ferrite Bead, 220 ohm @ 100 MHz, 2.5 A, 0603; Manufacturer: MuRata; Value: 220 ohm; Imax_A: 2.5A; DCR_ohm: 0.04; Value1: 0.04 ohm; ZTyp@100MHz_Ohm: 220; SizeArea_mm2: 1.28; SizeAreaWB_mm2: 4.68; SizeX_mm: 1.6; SizeY_mm: 0.8; SizeZ_mm: 1
NT1 = CMP-0078142-3: Single point connection between nets.
R11 R12 R16-R22 R24 R25 = CMP-0025697-4: RES, 0, 5%, 0.1 W, AEC-Q200 Grade 0, 0603; Manufacturer: Vishay-Dale; Power_W: 100mW; TempCo: 200 ppm/C; Value_Code: 0000; Value: 0; EIA_Code: E24; SizeX_mm: 1.6; SizeY_mm: 0.8; SizeZ_mm: 1; Value2: 0.1W; SizeArea_mm2: 1.28; AEC Qualified: Y; VDC_V: 75V; AEC Category: Q200
R13-R15 = CMP-0025813-4: RES, 470, 5%, 0.1 W, AEC-Q200 Grade 0, 0603; PartNumber: CRCW0603470RJNEA; Manufacturer: Vishay-Dale; Value: 470; Value_Code: 470R; Power_W: 100mW; Value2: 0.1W; VDC_V: 75V; TempCo: 200 ppm/C; EIA_Code: E24; SizeArea_mm2: 1.28; SizeX_mm: 1.6; SizeY_mm: 0.8; SizeZ_mm: 1; AEC Category: Q200; AEC Qualified: Y; AEC Grade: 0
TP8-TP18 = CMP-0003825-1: 1mm Test Point, SMT; Manufacturer: Any
TP19-TP26 = CMP-0055138-1: Test Point, Miniature, Black, TH; Manufacturer: Keystone; ContactFinish: Silver; CNHeader: FALSE; CT: TRUE; Green_Lifecycle: Active; Green_REACh: Passed

## Sheet LMK5C33414A_XO.SchDoc
size 431 x 279 mm; Date: Not shown in title block; ApprovedBy: Not shown in title block; CheckedBy: Not shown in title block; Author: Not shown in title block; CompanyName: Not shown in title block; Engineer: Not shown in title block; Organization: Not shown in title block; Address1: Not shown in title block; Address2: Not shown in title block; Address3: Not shown in title block; Address4: Not shown in title block; DocumentNumber: 1; Revision: Use project parameter SCH_Rev; SheetNumber: 2; SheetTotal: 3; PageSetup: Record=PageOptions¦CenterHorizontal=True¦CenterVertical=True¦PrintScale=1.00¦XCorrection=1.00¦YCorrection=1.00¦PrintKind=0¦BorderSize=5000000¦LeftOffset=0¦BottomOffset=0¦Orientation=2¦PaperLength=1000¦PaperWidth=1000¦Scale=100¦PaperSource=15¦PrintQuality=600¦MediaType=1¦DitherType=10¦PaperKind=Letter¦PrintScaleMode=1
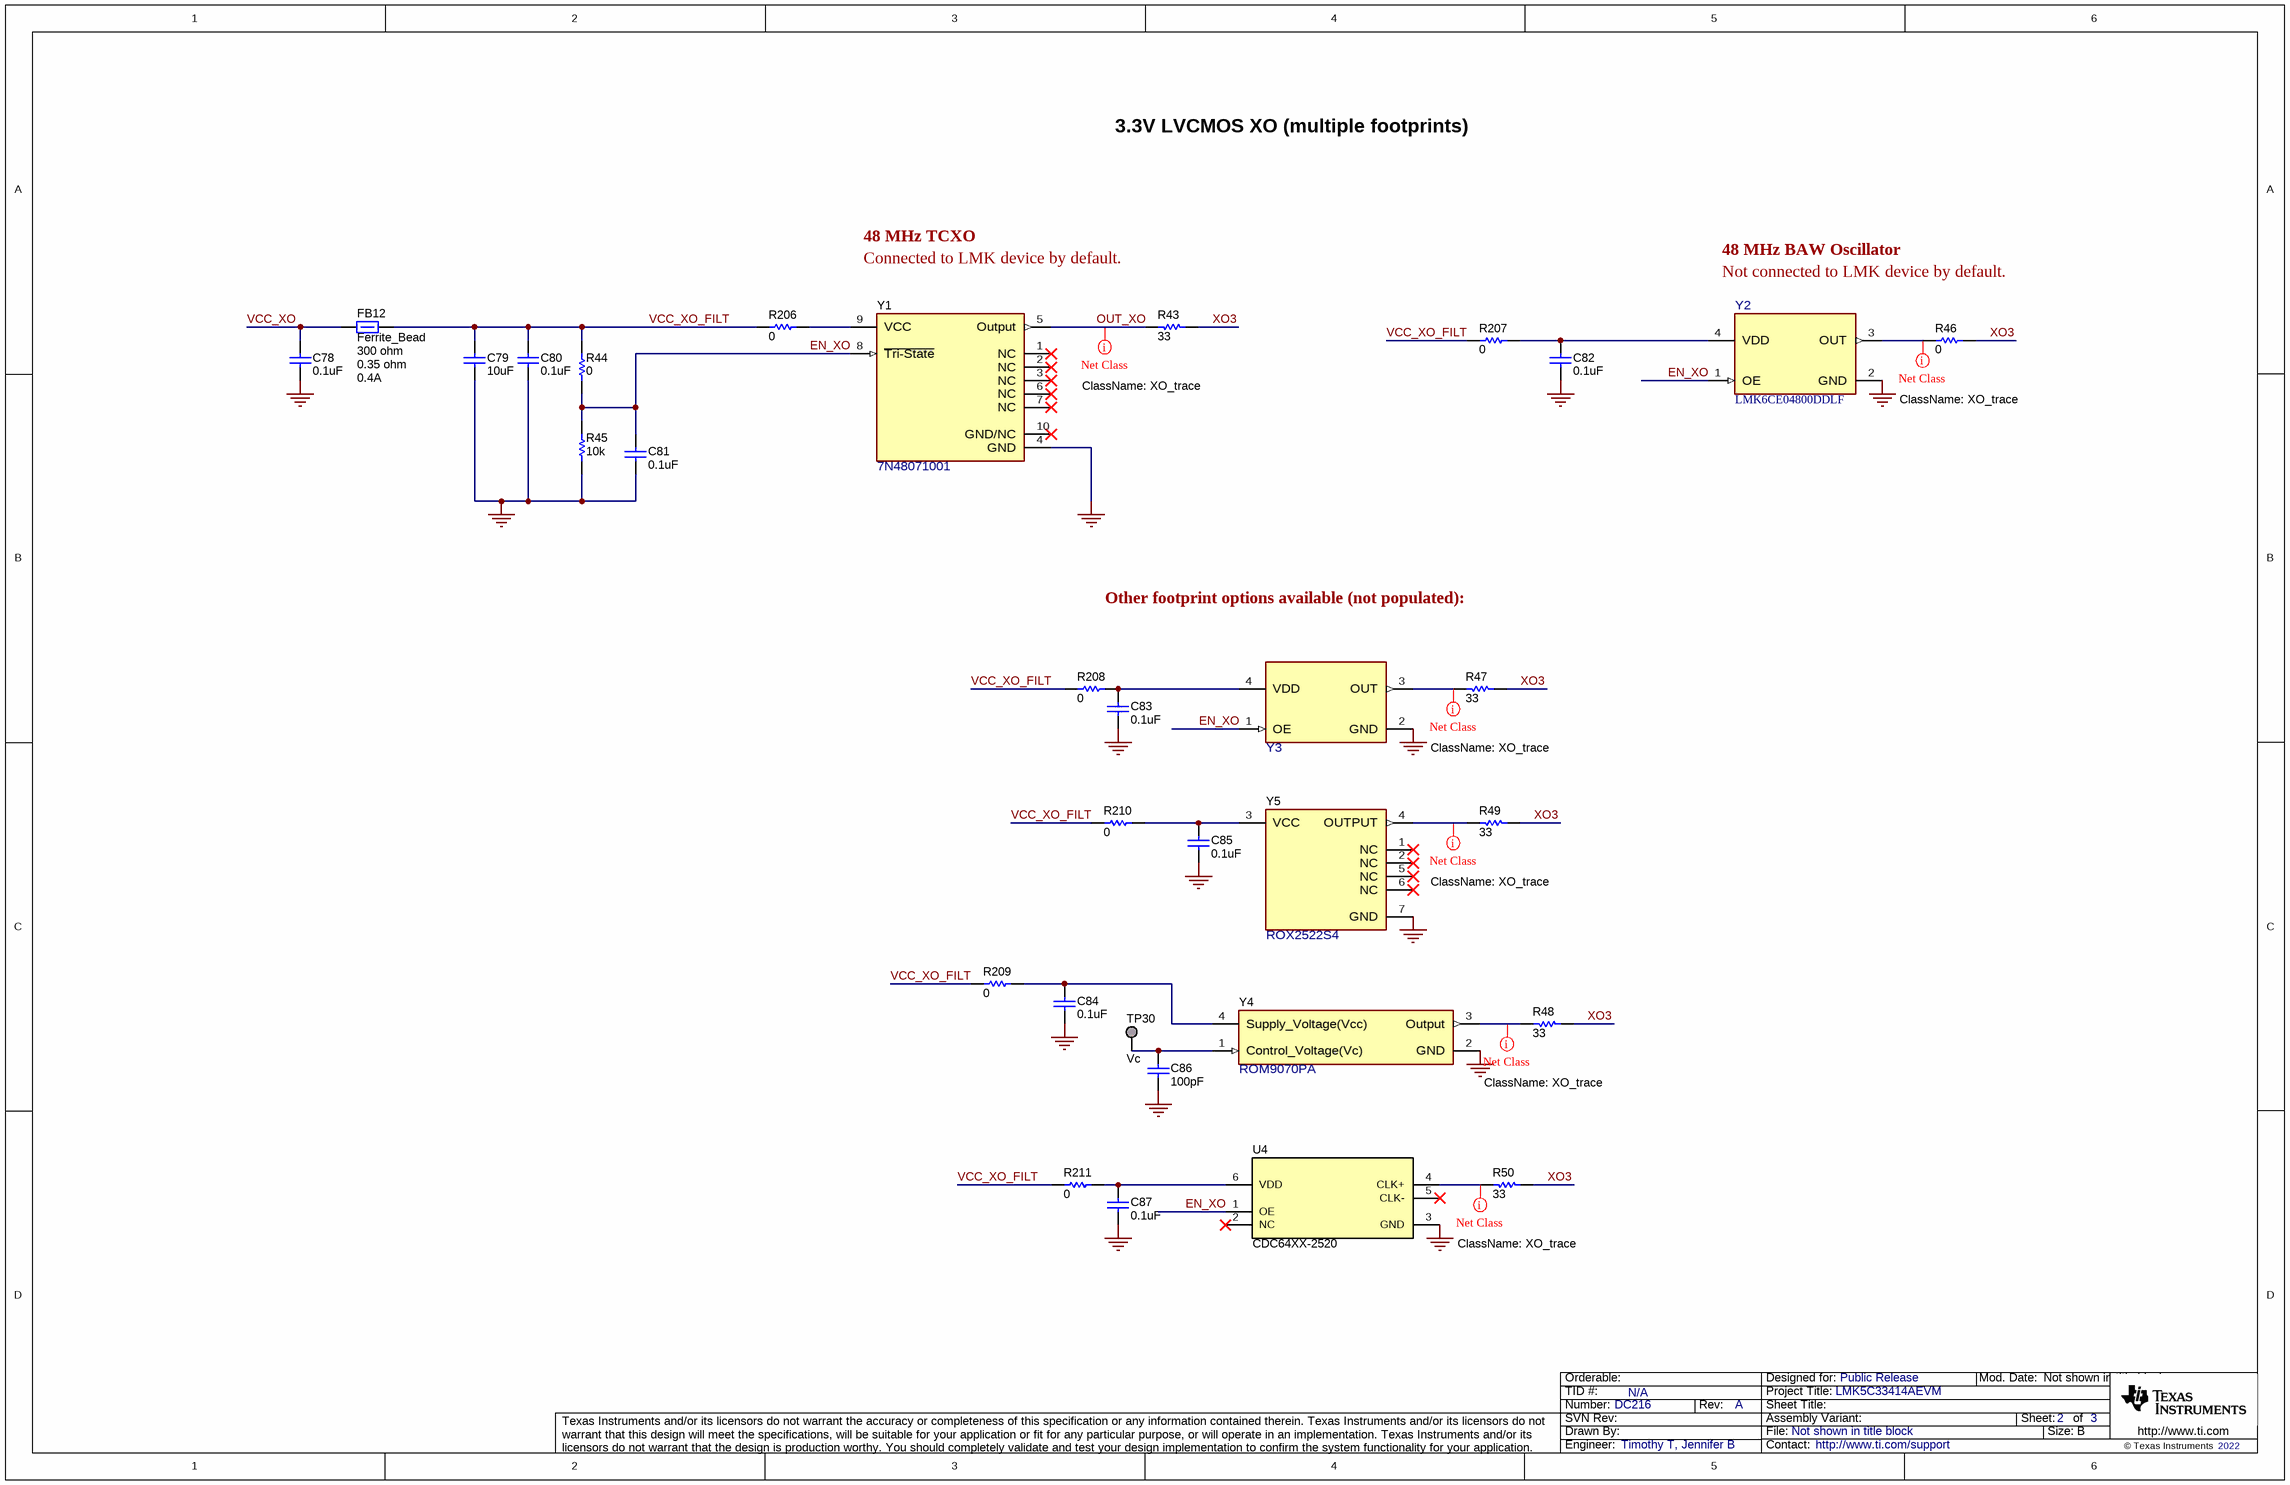
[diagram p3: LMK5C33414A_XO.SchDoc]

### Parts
C78  ValueDisplayed: 0.1uF  [0603]  (hidden comment: Capacitor)
C79  ValueDisplayed: 10uF  [0603]  (hidden comment: Capacitor)
C80  ValueDisplayed: 0.1uF  [0603]  (hidden comment: Capacitor)
C81  ValueDisplayed: 0.1uF  [0603]  (hidden comment: Capacitor)
C82  ValueDisplayed: 0.1uF  [0603]  (hidden comment: Capacitor)
C83  ValueDisplayed: 0.1uF  [0603]  (hidden comment: Capacitor)
C84  ValueDisplayed: 0.1uF  [0603]  (hidden comment: Capacitor)
C85  ValueDisplayed: 0.1uF  [0603]  (hidden comment: Capacitor)
C86  ValueDisplayed: 100pF  [0603]  (hidden comment: Capacitor)
C87  ValueDisplayed: 0.1uF  [0603]  (hidden comment: Capacitor)
FB12  Ferrite_Bead  value 300 ohm  Value1: 0.35 ohm  Value2: 0.4A  [LI0603D]
R43  ValueDisplayed: 33  [0402]  (hidden comment: CRCW040233R0JNED)
R44  ValueDisplayed: 0  [0603]  (hidden comment: ERJ-3GEY0R00V)
R45  ValueDisplayed: 10k  [0603]  (hidden comment: Resistor)
R46  ValueDisplayed: 0  [0402S]  (hidden comment: CRCW04020000Z0EDHP)
R47  ValueDisplayed: 33  [0402S]  (hidden comment: CRCW040233R0JNED)
R48  ValueDisplayed: 33  [0402S]  (hidden comment: CRCW040233R0JNED)
R49  ValueDisplayed: 33  [0402S]  (hidden comment: CRCW040233R0JNED)
R50  ValueDisplayed: 33  [0402S]  (hidden comment: CRCW040233R0JNED)
R206  ValueDisplayed: 0  [0603]  (hidden comment: RC0603JR-070RL)
R207  ValueDisplayed: 0  [0603]  (hidden comment: RC0603JR-070RL)
R208  ValueDisplayed: 0  [0603]  (hidden comment: RC0603JR-070RL)
R209  ValueDisplayed: 0  [0603]  (hidden comment: RC0603JR-070RL)
R210  ValueDisplayed: 0  [0603]  (hidden comment: RC0603JR-070RL)
R211  ValueDisplayed: 0  [0603]  (hidden comment: RC0603JR-070RL)
TP30  Vc  [Keystone_5019]
U4  CDC64XX-2520  [DLF0006A]
Y1  7N48071001  [FP-7N48071001_SMT10_7MM0_5MM0-MFG]
Y2  PartNumber: LMK6CE04800DDLF  [DLE0004A-MFG]  (hidden comment: LMK6CE04800ADLE)
Y3  7X-50.000MBB-T  [OSC_TXC-7X]  (value not drawn)
Y4  ROM9070PA  [FP-ROM9070PA_SMD4-MFG]
Y5  ROX2522S4  [FP-ROX2522S4_SMD_ OCXO7_25MM4_22MM0-MFG]

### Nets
GND: C78.2 C79.1 C80.2 C81.2 C82.2 C83.2 C84.2 C85.2 C86.2 C87.2 R45.2 U4.3(GND) Y1.4(GND) Y2.2(GND) Y3.2(GND) Y4.2(GND) Y5.7(GND)
VCC_XO: C78.1 FB12.2
EN_XO: C81.1 R44.2 R45.1 U4.1(OE) Y1.8(~{Tri-State}) Y2.1(OE) Y3.1(OE)
OUT_XO: R43.2 Y1.5(Output)
VCC_XO_FILT: C79.2 C80.1 FB12.1 R44.1 R206.1 R207.1 R208.1 R209.1 R210.1 R211.1
XO3: R43.1 R46.1 R47.1 R48.1 R49.1 R50.1
NetC82_1: C82.1 R207.2 Y2.4(VDD)
NetC83_1: C83.1 R208.2 Y3.4(VDD)
NetC84_1: C84.1 R209.2 Y4.4(Supply_Voltage(Vcc))
NetC85_1: C85.1 R210.2 Y5.3(VCC)
NetC86_1: C86.1 TP30.1 Y4.1(Control_Voltage(Vc))
NetC87_1: C87.1 R211.2 U4.6(VDD)
NetR46_2: R46.2 Y2.3(OUT)
NetR47_2: R47.2 Y3.3(OUT)
NetR48_2: R48.2 Y4.3(Output)
NetR49_2: R49.2 Y5.4(OUTPUT)
NetR50_2: R50.2 U4.4(CLK+)
NetR206_2: R206.2 Y1.9(VCC)

Not connected (* = marked no-connect by the designer): U4 2(NC)* 5(CLK-)*; Y1 1(NC)* 2(NC)* 3(NC)* 6(NC)* 7(NC)* 10(GND/NC)*; Y5 1(NC)* 2(NC)* 5(NC)* 6(NC)*

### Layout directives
net class XO_trace: NetR46_2, NetR47_2, NetR48_2, NetR49_2, NetR50_2, OUT_XO

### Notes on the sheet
- 3.3V LVCMOS XO (multiple footprints)
- 48 MHz TCXO
- Connected to LMK device by default.
- 48 MHz BAW Oscillator
- Not connected to LMK device by default.
- Other footprint options available (not populated):

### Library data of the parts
C78 C80-C85 C87 = CMP-0006856-6: CAP, CERM, 0.1 uF, 25 V, +/- 5%, X7R, 0603; Manufacturer: Kemet; PartNumber: C0603C104J3RACTU; Polarized: N; TaMax_C: 125°C; TaMin_C: -55°C; VDC_V: 25V; Cap_F: 100nF; Value: 0.1uF; Value1: Unknown; U/M: EA; AEC Category: Q200; SizeArea_mm2: 1.28; SizeAreaWB_mm2: 4.68; SizeX_mm: 1.6; SizeY_mm: 0.8; SizeZ_mm: 1
C79 = CMP-0007003-5: CAP, CERM, 10 uF, 10 V, +/- 20%, X5R, 0603; Manufacturer: TDK; PartNumber: C1608X5R1A106M080AC; ESR_ohm: 7.8m; IRMS_A: 1.85A; Polarized: N; TaMax_C: 85°C; TaMin_C: -55°C; VDC_V: 10V; Cap_F: 10µF; Value: 10uF; Value1: 0.0078 ohm; U/M: EA; SizeArea_mm2: 1.28; SizeAreaWB_mm2: 4.68; SizeX_mm: 1.6; SizeY_mm: 0.8; SizeZ_mm: 1; AEC Category: Q200
C86 = CMP-0006763-4: CAP, CERM, 100 pF, 50 V, +/- 5%, C0G/NP0, 0603; PartNumber: 06035A101JAT2A; Manufacturer: AVX; Polarized: N; Value: 100pF; U/M: EA; ESR_ohm: 1.19d; Value1: 0.119 ohm; VDC_V: 50V; TaMin_C: -55°C; TaMax_C: 125°C; AEC Category: Q200; SizeArea_mm2: 1.28; SizeAreaWB_mm2: 4.68; SizeX_mm: 1.6; SizeY_mm: 0.8; SizeZ_mm: 1
FB12 = CMP-0003403-1: Ferrite Bead, 300 ohm @ 100 MHz, 0.4 A, 1.6x0.8x0.95mm; PartNumber: LI0603D301R-10; Manufacturer: Laird-Signal Integrity Products; Imax_A: 4dA; DCR_ohm: 3.5d; ZTyp@100MHz_Ohm: 300; SizeArea_mm2: 1.28; SizeAreaWB_mm2: 4.68; SizeX_mm: 1.6; SizeY_mm: 0.8; SizeZ_mm: 0.95
R43 R47-R50 = CMP-0026908-3: RES, 33, 5%, 0.063 W, AEC-Q200 Grade 0, 0402; Manufacturer: Vishay-Dale; VDC_V: 50V; Power_W: 63mW; Value: 33; Value_Code: 33R0; Value2: 0.063W; EIA_Code: E24; TempCo: 200 ppm/C; AEC Category: Q200; AEC Qualified: Y; AEC Grade: 0; SizeArea_mm2: 0.5; SizeX_mm: 1; SizeZ_mm: 0.6
R44 = CMP-0025874-4: RES, 0, 5%, 0.1 W, AEC-Q200 Grade 0, 0603; Manufacturer: Panasonic; CompType: Resistor; VDC_V: 50V; Power_W: 100mW; Value: 0; Value_Code: 0000; Value2: 0.1W; EIA_Code: E24; TempCo: 600 ppm/C; AEC Category: Q200; AEC Qualified: Y; SizeArea_mm2: 1.28; SizeX_mm: 1.6; SizeY_mm: 0.8; SizeZ_mm: 1; SizeAreaWB_mm2: 4.68
R45 = CMP-0025701-4: RES, 10 k, 5%, 0.1 W, AEC-Q200 Grade 0, 0603; Manufacturer: Vishay-Dale; PartNumber: CRCW060310K0JNEA; VDC_V: 75V; Power_W: 100mW; Value: 10k; Value_Code: 10k0; Value2: 0.1W; EIA_Code: E24; TempCo: 200 ppm/C; AEC Category: Q200; AEC Qualified: Y; AEC Grade: 0; SizeArea_mm2: 1.28; SizeX_mm: 1.6; SizeY_mm: 0.8; SizeZ_mm: 1
R46 = CMP-0081856-1: RES, 0, 0%, 0.2 W, AEC-Q200 Grade 0, 0402; Manufacturer: Vishay-Dale; VDC_V: 50V; Power_W: 200mW; Value: 0; Value2: 0.2W; AEC Category: Q200; AEC Qualified: Y; SizeArea_mm2: 0.5; SizeX_mm: 1; SizeZ_mm: 0.6; SizeAreaWB_mm2: 3
R206-R211 = CMP-0025885-5: RES, 0, 5%, 0.1 W, 0603; Manufacturer: Yageo; Power_W: 100mW; TempCo: 200 ppm/C; Value_Code: 0000; Value: 0; EIA_Code: E24; SizeX_mm: 1.6; SizeY_mm: 0.8; SizeZ_mm: 1; Value2: 0.1W; SizeArea_mm2: 1.28; AEC Qualified: N; AEC Category: Q200; VDC_V: 75V; SizeAreaWB_mm2: 4.68
TP30 = CMP-0055162-1: Test Point, Miniature, SMT; Manufacturer: Keystone; PartNumber: 5019; CNHeader: FALSE; Green_Lifecycle: Active; Green_REACh: Passed; CT: TRUE
U4 = CMP-0078850-3: CDC64XX-2520, DLF0006A (VSON-6); Alternate Manufacturer: Texas Instruments; SizeZ_mm: 1; AEC Qualified: N; SizeArea_mm2: 5; SizeY_mm: 2.5; AEC Category: Q200; SizeAreaWB_mm2: 10.5; SizeX_mm: 2; CompType: IC
Y1 = CMP-0093851-1: SMD TCXO 7.0 * 5.0 48.000000MHz; Manufacturer: TXC; Frequency Stability: 0.25ppm; Frequency_Fixed: 48MHz; SizeZ_mm: 1.7mm; AEC Qualified: No; Load Capacitance: 15pF; Min Supply Voltage: 2.97V; Max Supply Voltage: 3.63V; Max Supply Current: 10mA
Y2 = CMP-0096255-1: High-Performance BAW Oscillator, LVCMOS; <1ps, +/- 50ppm; 2.5V/3.3V, -40C to 105C and DLE package; Manufacturer: Texas Instruments; Max Supply Voltage: 3.465V; TaMax_C: +105°C; Standoff Height: 0mm; SizeZ_mm: 1mm; TaMin_C: -40°C; Frequency_Fixed: 48MHz; AEC Qualified: No; TJmax_C: +125°C; Load Capacitance: 30pF; Min Supply Voltage: 2.375V
Y3 = CMP-0096255-1: Crystal, Sealed Locked 50 MHz, 15pF, SMD; Manufacturer: Texas Instruments; PartNumber: LMK6CE04800ADLE; TaMin_C: -40°C; Frequency Stability: +/-50ppm; Frequency_Fixed: 50MHz; TaMax_C: +105°C; SizeZ_mm: 1mm; Load Capacitance: 30pF; CompType: Oscillator; Max Supply Voltage: 3.465V; Min Supply Voltage: 2.375V; Standoff Height: 0mm; TJmax_C: +125°C
Y4 = CMP-0088752-1: MERCURY+ 38.88MHz OCXO CMOS Oscillator 2.7 ~ 5V 4-SMD; Manufacturer: Rakon; AEC Qualified: No; SizeZ_mm: 4.1mm; Min Supply Voltage: 2.7V; Frequency Stability: 0.01ppm
Y5 = CMP-0088753-1: STANDARD OCXO 10MHz Frequency; Manufacturer: Rakon; Max Supply Voltage: 3.465V; SizeZ_mm: 15.4mm; Min Supply Voltage: 3.135V; AEC Qualified: No

## Sheet LMK5C33414A_Inputs.SchDoc
size 431 x 279 mm; Date: Not shown in title block; ApprovedBy: Not shown in title block; CheckedBy: Not shown in title block; Author: Not shown in title block; CompanyName: Not shown in title block; Engineer: Not shown in title block; Organization: Not shown in title block; Address1: Not shown in title block; Address2: Not shown in title block; Address3: Not shown in title block; Address4: Not shown in title block; DocumentNumber: 2; Revision: Use project parameter SCH_Rev; SheetNumber: 2; SheetTotal: 3; PageSetup: Record=PageOptions¦CenterHorizontal=True¦CenterVertical=True¦PrintScale=1.00¦XCorrection=1.00¦YCorrection=1.00¦PrintKind=0¦BorderSize=5000000¦LeftOffset=0¦BottomOffset=0¦Orientation=2¦PaperLength=1000¦PaperWidth=1000¦Scale=100¦PaperSource=15¦PrintQuality=600¦MediaType=1¦DitherType=10¦PaperKind=Letter¦PrintScaleMode=1
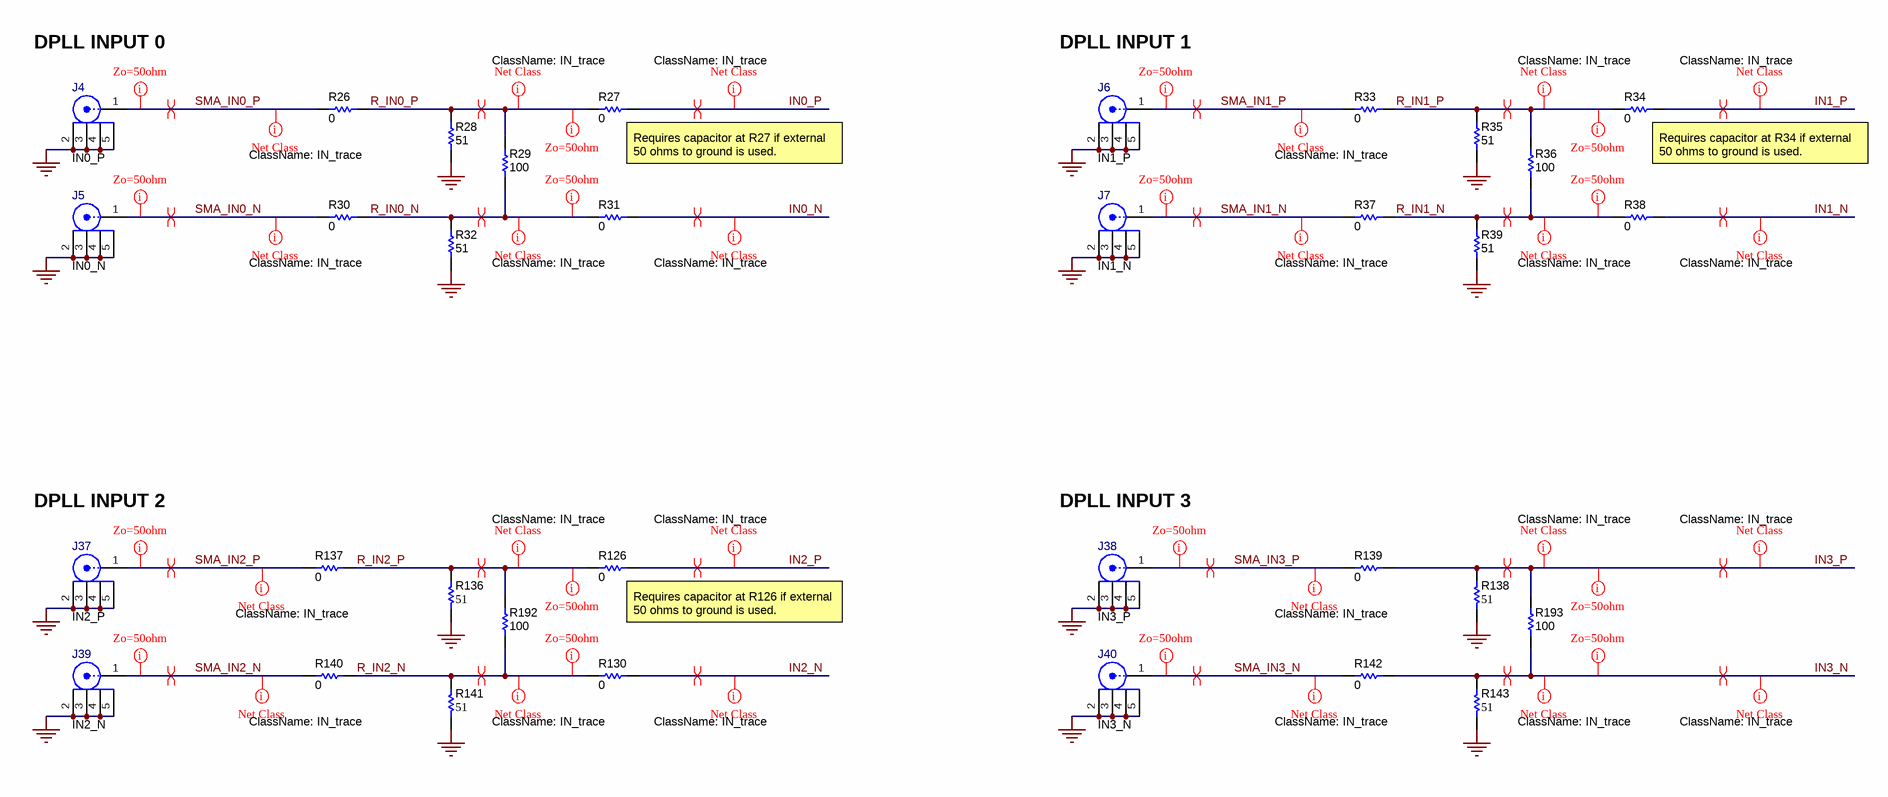
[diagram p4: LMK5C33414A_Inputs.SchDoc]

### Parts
J4  IN0_P  [FP-CON-SMA-EDGE-S_CONN_JACK-MFG]
J5  IN0_N  [FP-CON-SMA-EDGE-S_CONN_JACK-MFG]
J6  IN1_P  [FP-CON-SMA-EDGE-S_CONN_JACK-MFG]
J7  IN1_N  [FP-CON-SMA-EDGE-S_CONN_JACK-MFG]
J37  IN2_P  [FP-CON-SMA-EDGE-S_CONN_JACK-MFG]
J38  IN3_P  [FP-CON-SMA-EDGE-S_CONN_JACK-MFG]
J39  IN2_N  [FP-CON-SMA-EDGE-S_CONN_JACK-MFG]
J40  IN3_N  [FP-CON-SMA-EDGE-S_CONN_JACK-MFG]
R26  ValueDisplayed: 0  [0402L]  (hidden comment: CRCW04020000Z0EDHP)
R27  ValueDisplayed: 0  [0402L]  (hidden comment: CRCW04020000Z0EDHP)
R28  ValueDisplayed: 51  [0402S]  (hidden comment: RC0402JR-0751RL)
R29  ValueDisplayed: 100  [0603S]  (hidden comment: CRCW0603100RFKEA)
R30  ValueDisplayed: 0  [0402L]  (hidden comment: CRCW04020000Z0EDHP)
R31  ValueDisplayed: 0  [0402L]  (hidden comment: CRCW04020000Z0EDHP)
R32  ValueDisplayed: 51  [0402S]  (hidden comment: RC0402JR-0751RL)
R33  ValueDisplayed: 0  [0402L]  (hidden comment: CRCW04020000Z0EDHP)
R34  ValueDisplayed: 0  [0402L]  (hidden comment: CRCW04020000Z0EDHP)
R35  ValueDisplayed: 51  [0402S]  (hidden comment: RC0402JR-0751RL)
R36  ValueDisplayed: 100  [0603S]  (hidden comment: CRCW0603100RFKEA)
R37  ValueDisplayed: 0  [0402L]  (hidden comment: CRCW04020000Z0EDHP)
R38  ValueDisplayed: 0  [0402L]  (hidden comment: CRCW04020000Z0EDHP)
R39  ValueDisplayed: 51  [0402S]  (hidden comment: RC0402JR-0751RL)
R126  ValueDisplayed: 0  [0402L]  (hidden comment: RK73Z1ETTP)
R130  ValueDisplayed: 0  [0402L]  (hidden comment: RK73Z1ETTP)
R136  ValueDisplayed: 51  [0402S]  (hidden comment: RC0402JR-0751RL)
R137  ValueDisplayed: 0  [0402L]  (hidden comment: CRCW04020000Z0EDHP)
R138  ValueDisplayed: 51  [0402S]  (hidden comment: RC0402JR-0751RL)
R139  ValueDisplayed: 0  [0402L]  (hidden comment: CRCW04020000Z0EDHP)
R140  ValueDisplayed: 0  [0402L]  (hidden comment: CRCW04020000Z0EDHP)
R141  ValueDisplayed: 51  [0402S]  (hidden comment: RC0402JR-0751RL)
R142  ValueDisplayed: 0  [0402L]  (hidden comment: CRCW04020000Z0EDHP)
R143  ValueDisplayed: 51  [0402S]  (hidden comment: RC0402JR-0751RL)
R192  ValueDisplayed: 100  [0402L]  (hidden comment: CRCW0402100RFKED)
R193  ValueDisplayed: 100  [0402L]  (hidden comment: CRCW0402100RFKED)

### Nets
GND: J4.2 J4.3 J4.4 J4.5 J5.2 J5.3 J5.4 J5.5 J6.2 J6.3 J6.4 J6.5 J7.2 J7.3 J7.4 J7.5 J37.2 J37.3 J37.4 J37.5 J38.2 J38.3 J38.4 J38.5 J39.2 J39.3 J39.4 J39.5 J40.2 J40.3 J40.4 J40.5 R28.1 R32.1 R35.1 R39.1 R136.2 R138.2 R141.2 R143.2
IN0_N: R31.2
IN0_P: R27.2
IN1_N: R38.2
IN1_P: R34.2
IN2_N: R130.1
IN2_P: R126.1
IN3_N: R142.2 R143.1 R193.1
IN3_P: R138.1 R139.2 R193.2
R_IN0_N: R29.1 R30.2 R31.1 R32.2
R_IN0_P: R26.2 R27.1 R28.2 R29.2
R_IN1_N: R36.1 R37.2 R38.1 R39.2
R_IN1_P: R33.2 R34.1 R35.2 R36.2
R_IN2_N: R130.2 R140.2 R141.1 R192.1
R_IN2_P: R126.2 R136.1 R137.2 R192.2
SMA_IN0_N: J5.1 R30.1
SMA_IN0_P: J4.1 R26.1
SMA_IN1_N: J7.1 R37.1
SMA_IN1_P: J6.1 R33.1
SMA_IN2_N: J39.1 R140.1
SMA_IN2_P: J37.1 R137.1
SMA_IN3_N: J40.1 R142.1
SMA_IN3_P: J38.1 R139.1

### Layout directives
rule Impedance Constraint [Min = 45.00    Max = 55.00    ]: IN3_N, IN3_P, R_IN0_N, R_IN0_P, R_IN1_N, R_IN1_P, R_IN2_N, R_IN2_P, SMA_IN0_N, SMA_IN0_P, SMA_IN1_N, SMA_IN1_P, SMA_IN2_N, SMA_IN2_P, SMA_IN3_N, SMA_IN3_P
differential pair: IN0_N, IN0_P, IN1_N, IN1_P, IN2_N, IN2_P, IN3_N, IN3_P, R_IN0_N, R_IN0_P, R_IN1_N, R_IN1_P, R_IN2_N, R_IN2_P, SMA_IN0_N, SMA_IN0_P, SMA_IN1_N, SMA_IN1_P, SMA_IN2_N, SMA_IN2_P, SMA_IN3_N, SMA_IN3_P
net class IN_trace: IN0_N, IN0_P, IN1_N, IN1_P, IN2_N, IN2_P, IN3_N, IN3_P, R_IN0_N, R_IN0_P, R_IN1_N, R_IN1_P, R_IN2_N, R_IN2_P, SMA_IN0_N, SMA_IN0_P, SMA_IN1_N, SMA_IN1_P, SMA_IN2_N, SMA_IN2_P, SMA_IN3_N, SMA_IN3_P

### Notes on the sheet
- DPLL INPUT 0
- DPLL INPUT 1
- (near R27) Requires capacitor at R27 if external 50 ohms to ground is used.
- (near R34) Requires capacitor at R34 if external 50 ohms to ground is used.
- DPLL INPUT 2
- DPLL INPUT 3
- (near R126) Requires capacitor at R126 if external 50 ohms to ground is used.

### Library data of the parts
J4-J7 J37-J40 = CMP-0088000-4: as J2 on sheet LMK5C33414A_Power
R26 R30 R31 R33 R37 R38 R137 R139 R140 R142 = CMP-0081856-1: as R46 on sheet LMK5C33414A_XO
R27 R34 = CMP-0081856-1: RES, 0, 0%, 0.2 W, AEC-Q200 Grade 0, 0402; Manufacturer: Vishay-Dale; CompType: Resistor; VDC_V: 50V; Power_W: 200mW; Value: 0; Value2: 0.2W; AEC Category: Q200; AEC Qualified: Y; SizeArea_mm2: 0.5; SizeX_mm: 1; SizeZ_mm: 0.6; SizeAreaWB_mm2: 3
R28 R32 R35 R39 = CMP-0027006-2: RES, 51, 5%, 0.0625 W, 0402; Manufacturer: Yageo America; Value: 51; Value_Code: 51R0; Power_W: 62.5mW; VDC_V: 50V; TempCo: 100 ppm/C; EIA_Code: E24; AEC Category: Q200; AEC Qualified: N; SizeArea_mm2: 0.5; SizeX_mm: 1; SizeZ_mm: 0.6; U/M: EA
R29 R36 = CMP-0021991-4: RES, 100, 1%, 0.1 W, AEC-Q200 Grade 0, 0603; Manufacturer: Vishay-Dale; Value: 100; Value_Code: 100R; Power_W: 100mW; Value2: 0.1W; VDC_V: 75V; TempCo: 100 ppm/C; EIA_Code: E96; AEC Category: Q200; AEC Qualified: Y; AEC Grade: 0; SizeArea_mm2: 1.28; SizeX_mm: 1.6; SizeY_mm: 0.8; SizeZ_mm: 1
R126 R130 = CMP-0027007-2: RES, 0, 5%, 0.063 W, AEC-Q200 Grade 0, 0402; Manufacturer: KOA Speer; Power_W: 63mW; TempCo: ppm/C; Value_Code: 0000; U/M: EA; Value: 0; EIA_Code: E24; SizeX_mm: 1; SizeY_mm: 0.5; SizeZ_mm: 0.6; Value2: 0.063W; CompType: Resistor; AEC Qualified: Y; AEC Category: Q200
R136 R138 R141 R143 = CMP-0027006-2: RES, 51, 5%, 0.0625 W, 0402; Manufacturer: Yageo America; Power_W: 62.5mW; TempCo: 100 ppm/C; Value_Code: 51R0; Value: 51; EIA_Code: E24; SizeX_mm: 1; SizeY_mm: 0.5; SizeZ_mm: 0.6; AEC Qualified: N; VDC_V: 50V; AEC Category: Q200; U/M: EA
R192 R193 = CMP-0025951-3: RES, 100, 1%, 0.063 W, AEC-Q200 Grade 0, 0402; Manufacturer: Vishay-Dale; CompType: Resistor; Value: 100; Value_Code: 100R; Power_W: 63mW; Value2: 0.063W; VDC_V: 50V; TempCo: 100 ppm/C; EIA_Code: E96; AEC Category: Q200; AEC Qualified: Y; AEC Grade: 0; SizeArea_mm2: 0.5; SizeX_mm: 1; SizeZ_mm: 0.6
